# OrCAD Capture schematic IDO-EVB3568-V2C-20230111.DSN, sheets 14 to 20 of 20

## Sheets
14 P15. Ethernet-GEPHY_RGMII1_M1: size A2; title: IDO-EVB3568-V2; note: Ethernet-GEPHY_RGMII1
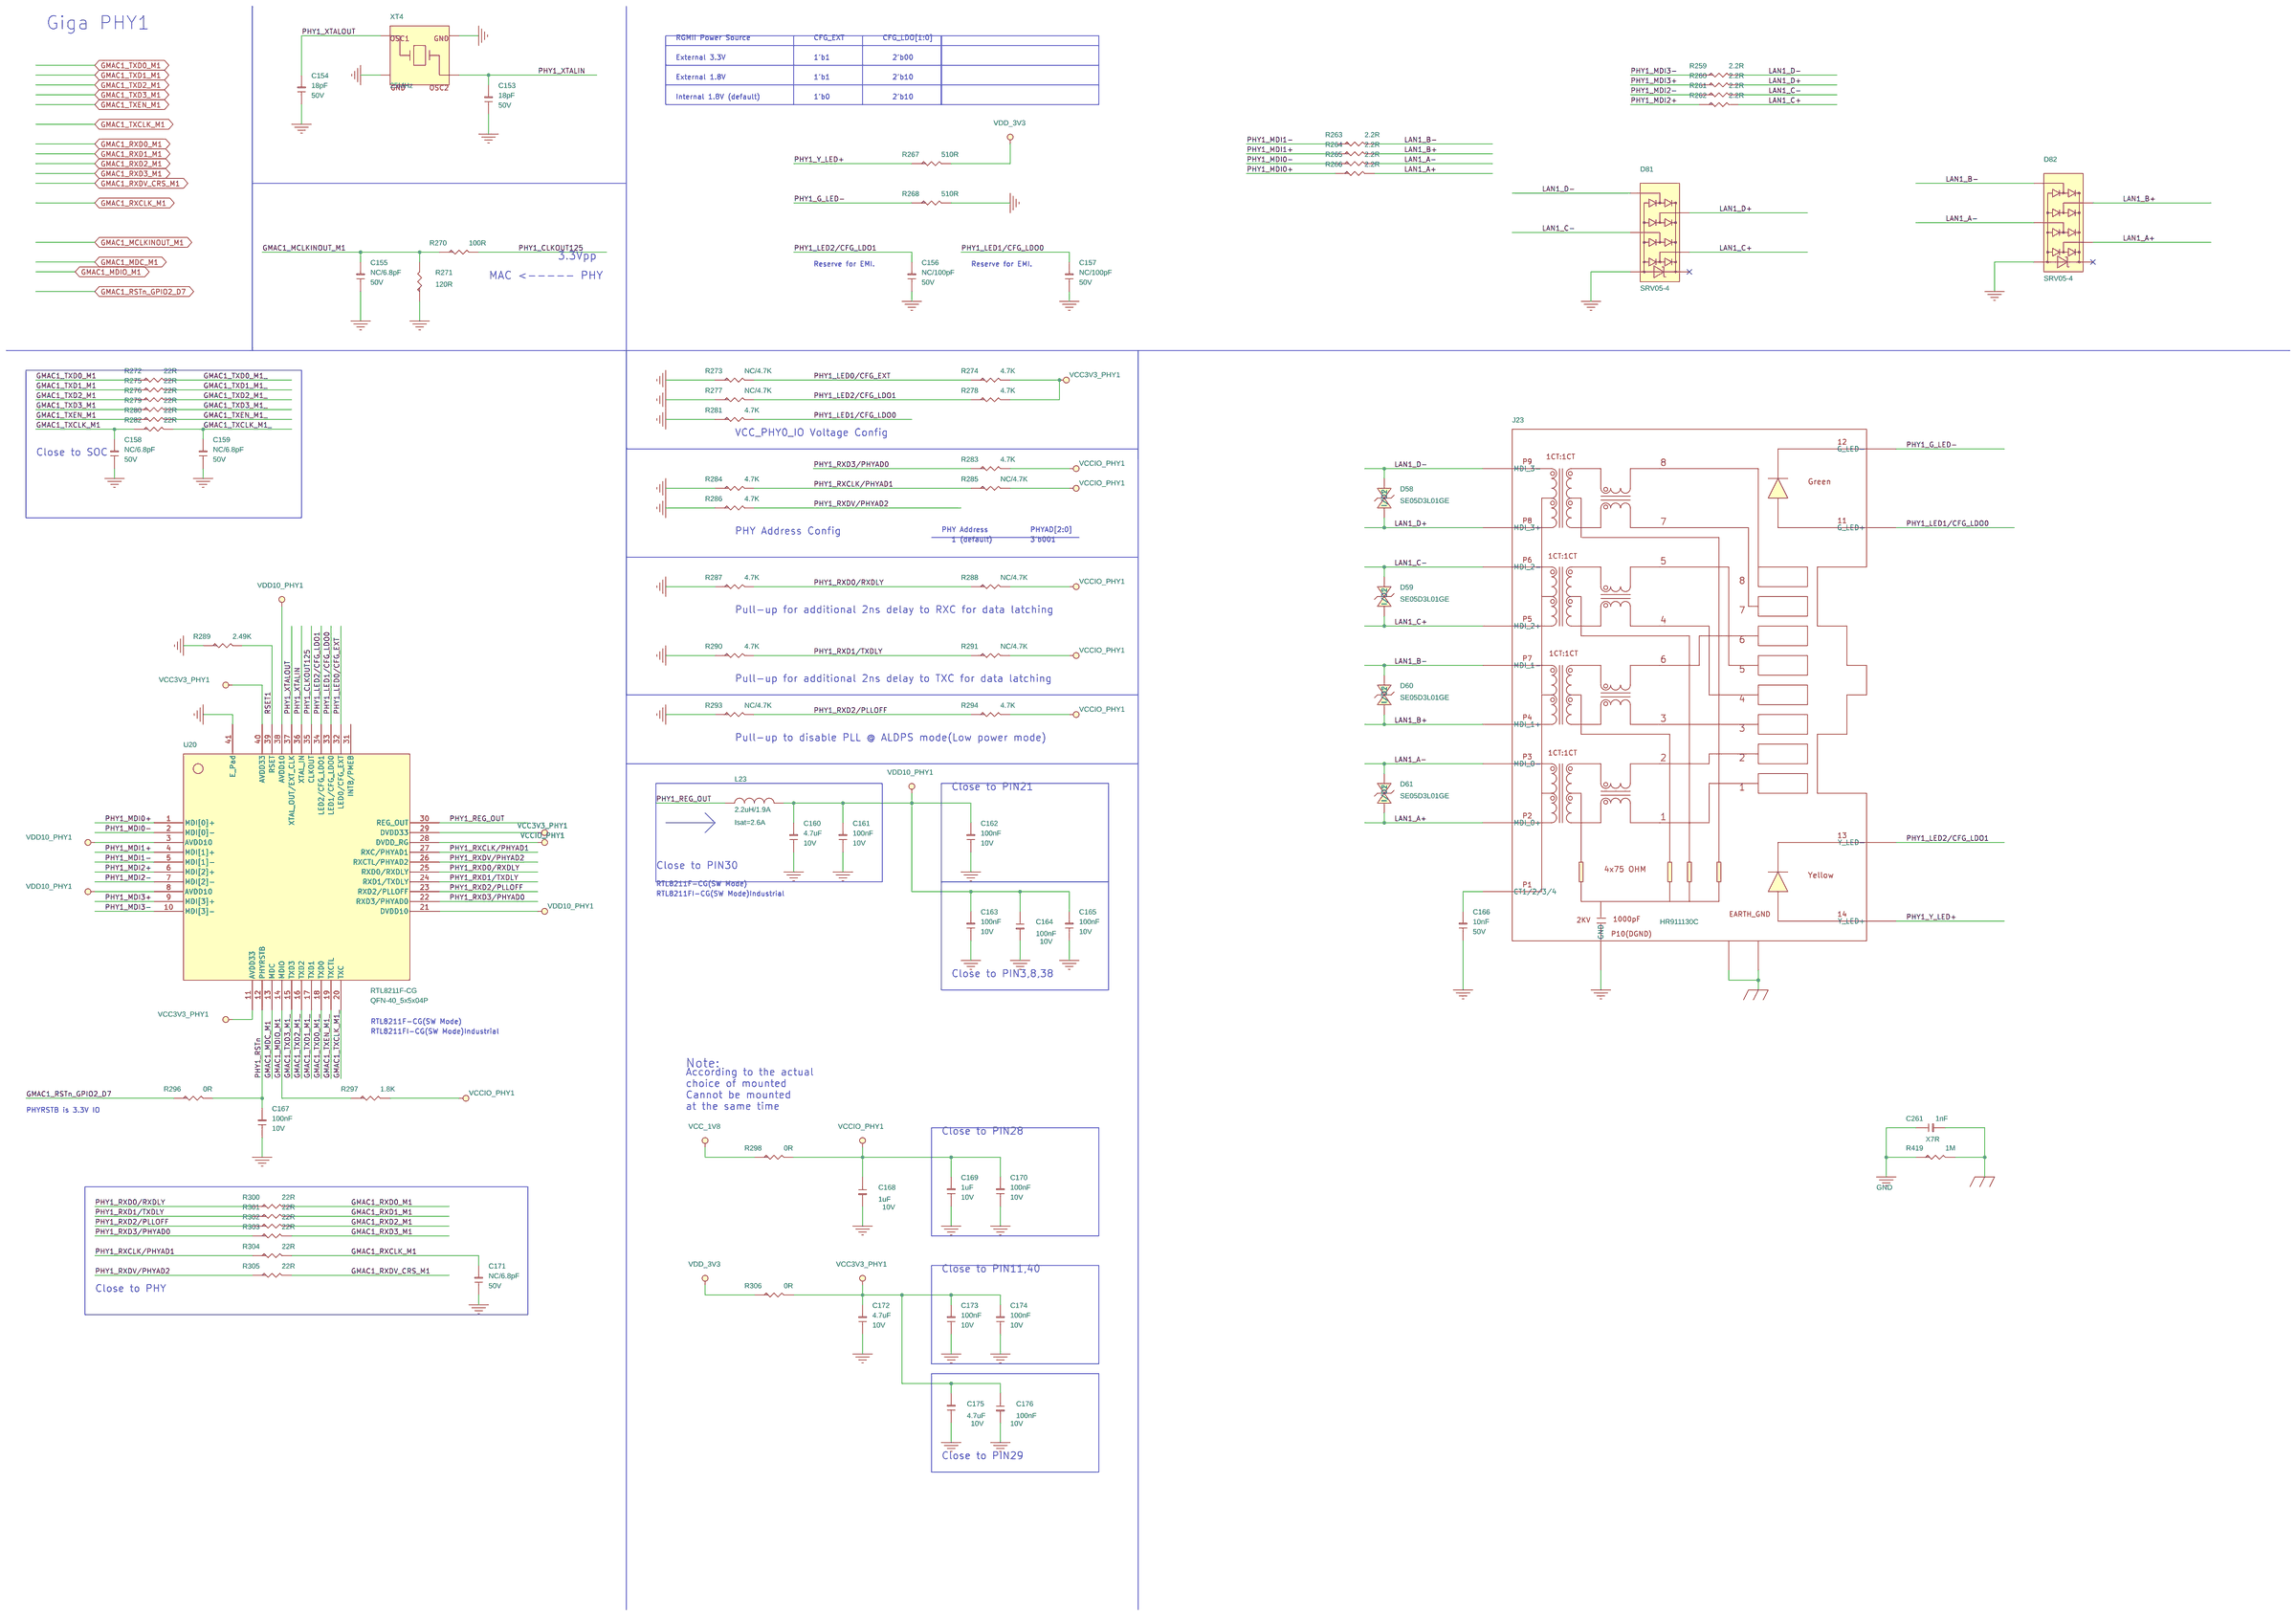
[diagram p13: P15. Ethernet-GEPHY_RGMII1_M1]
15 P16. IO: size A3; title: EST3568-V2; note: IO扩展
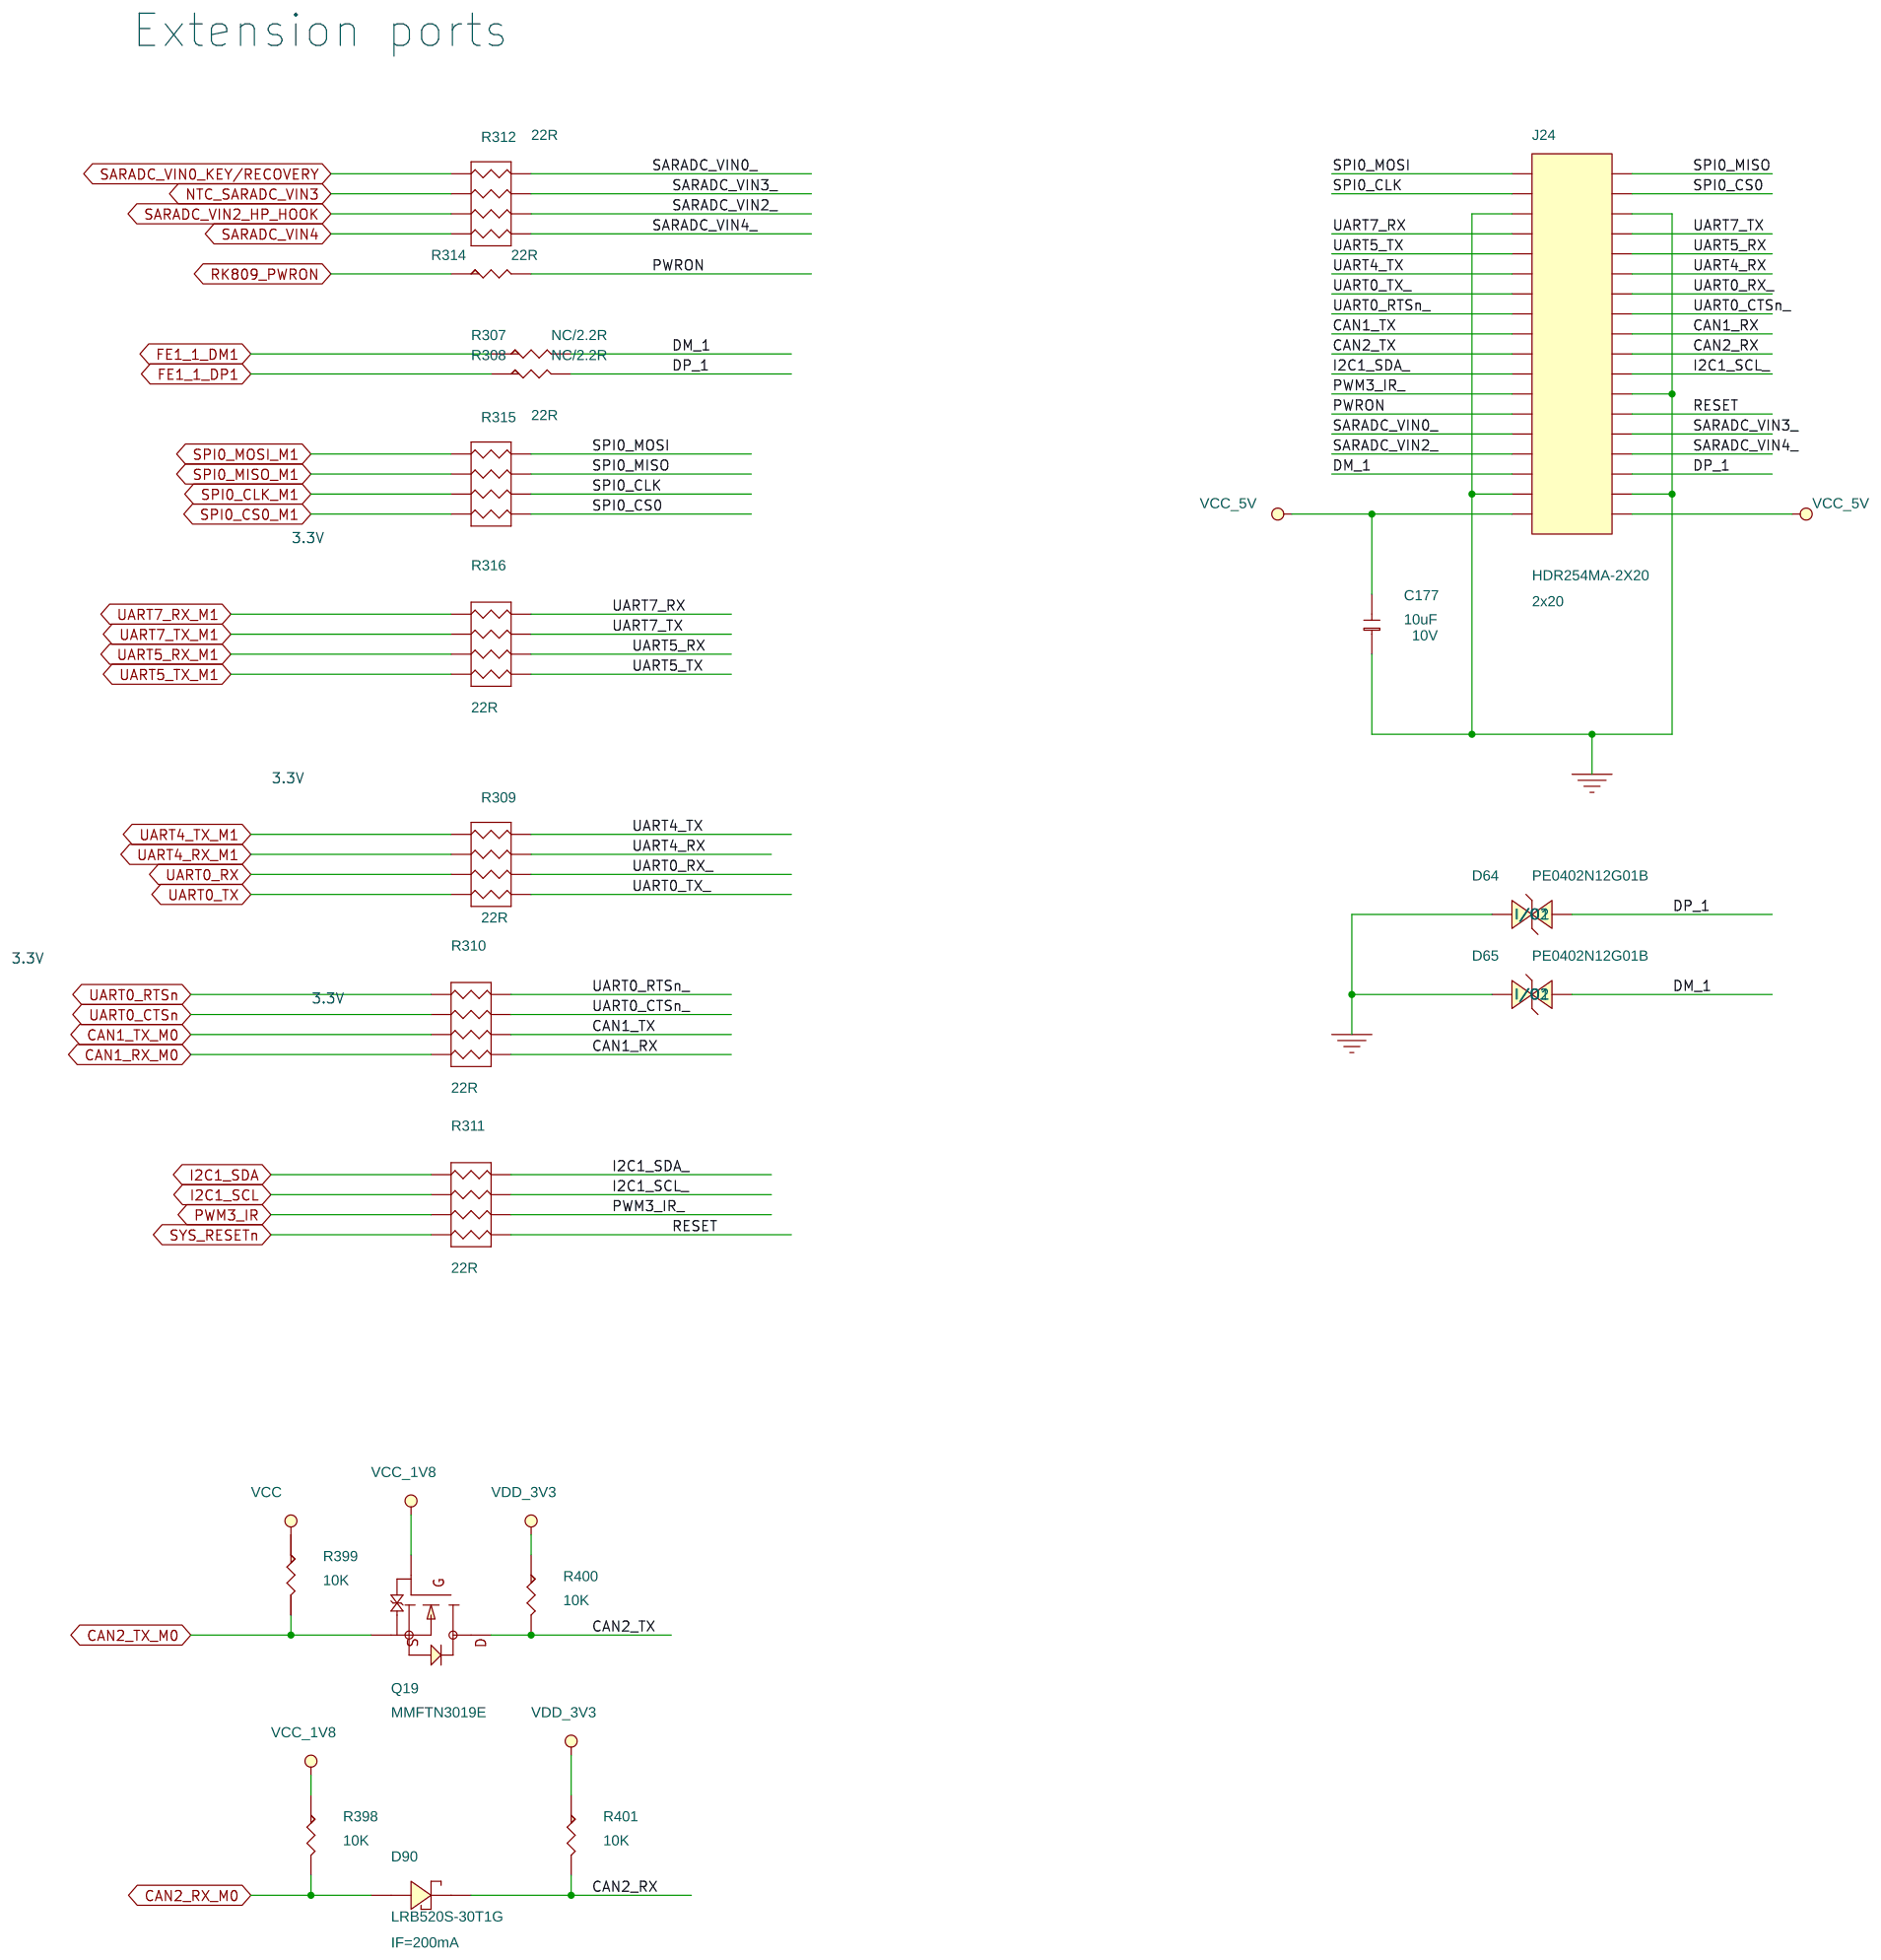
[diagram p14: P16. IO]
16 P19.PCIE2.0: size A3; title: EST3568-V2; note: MINI_PCIE
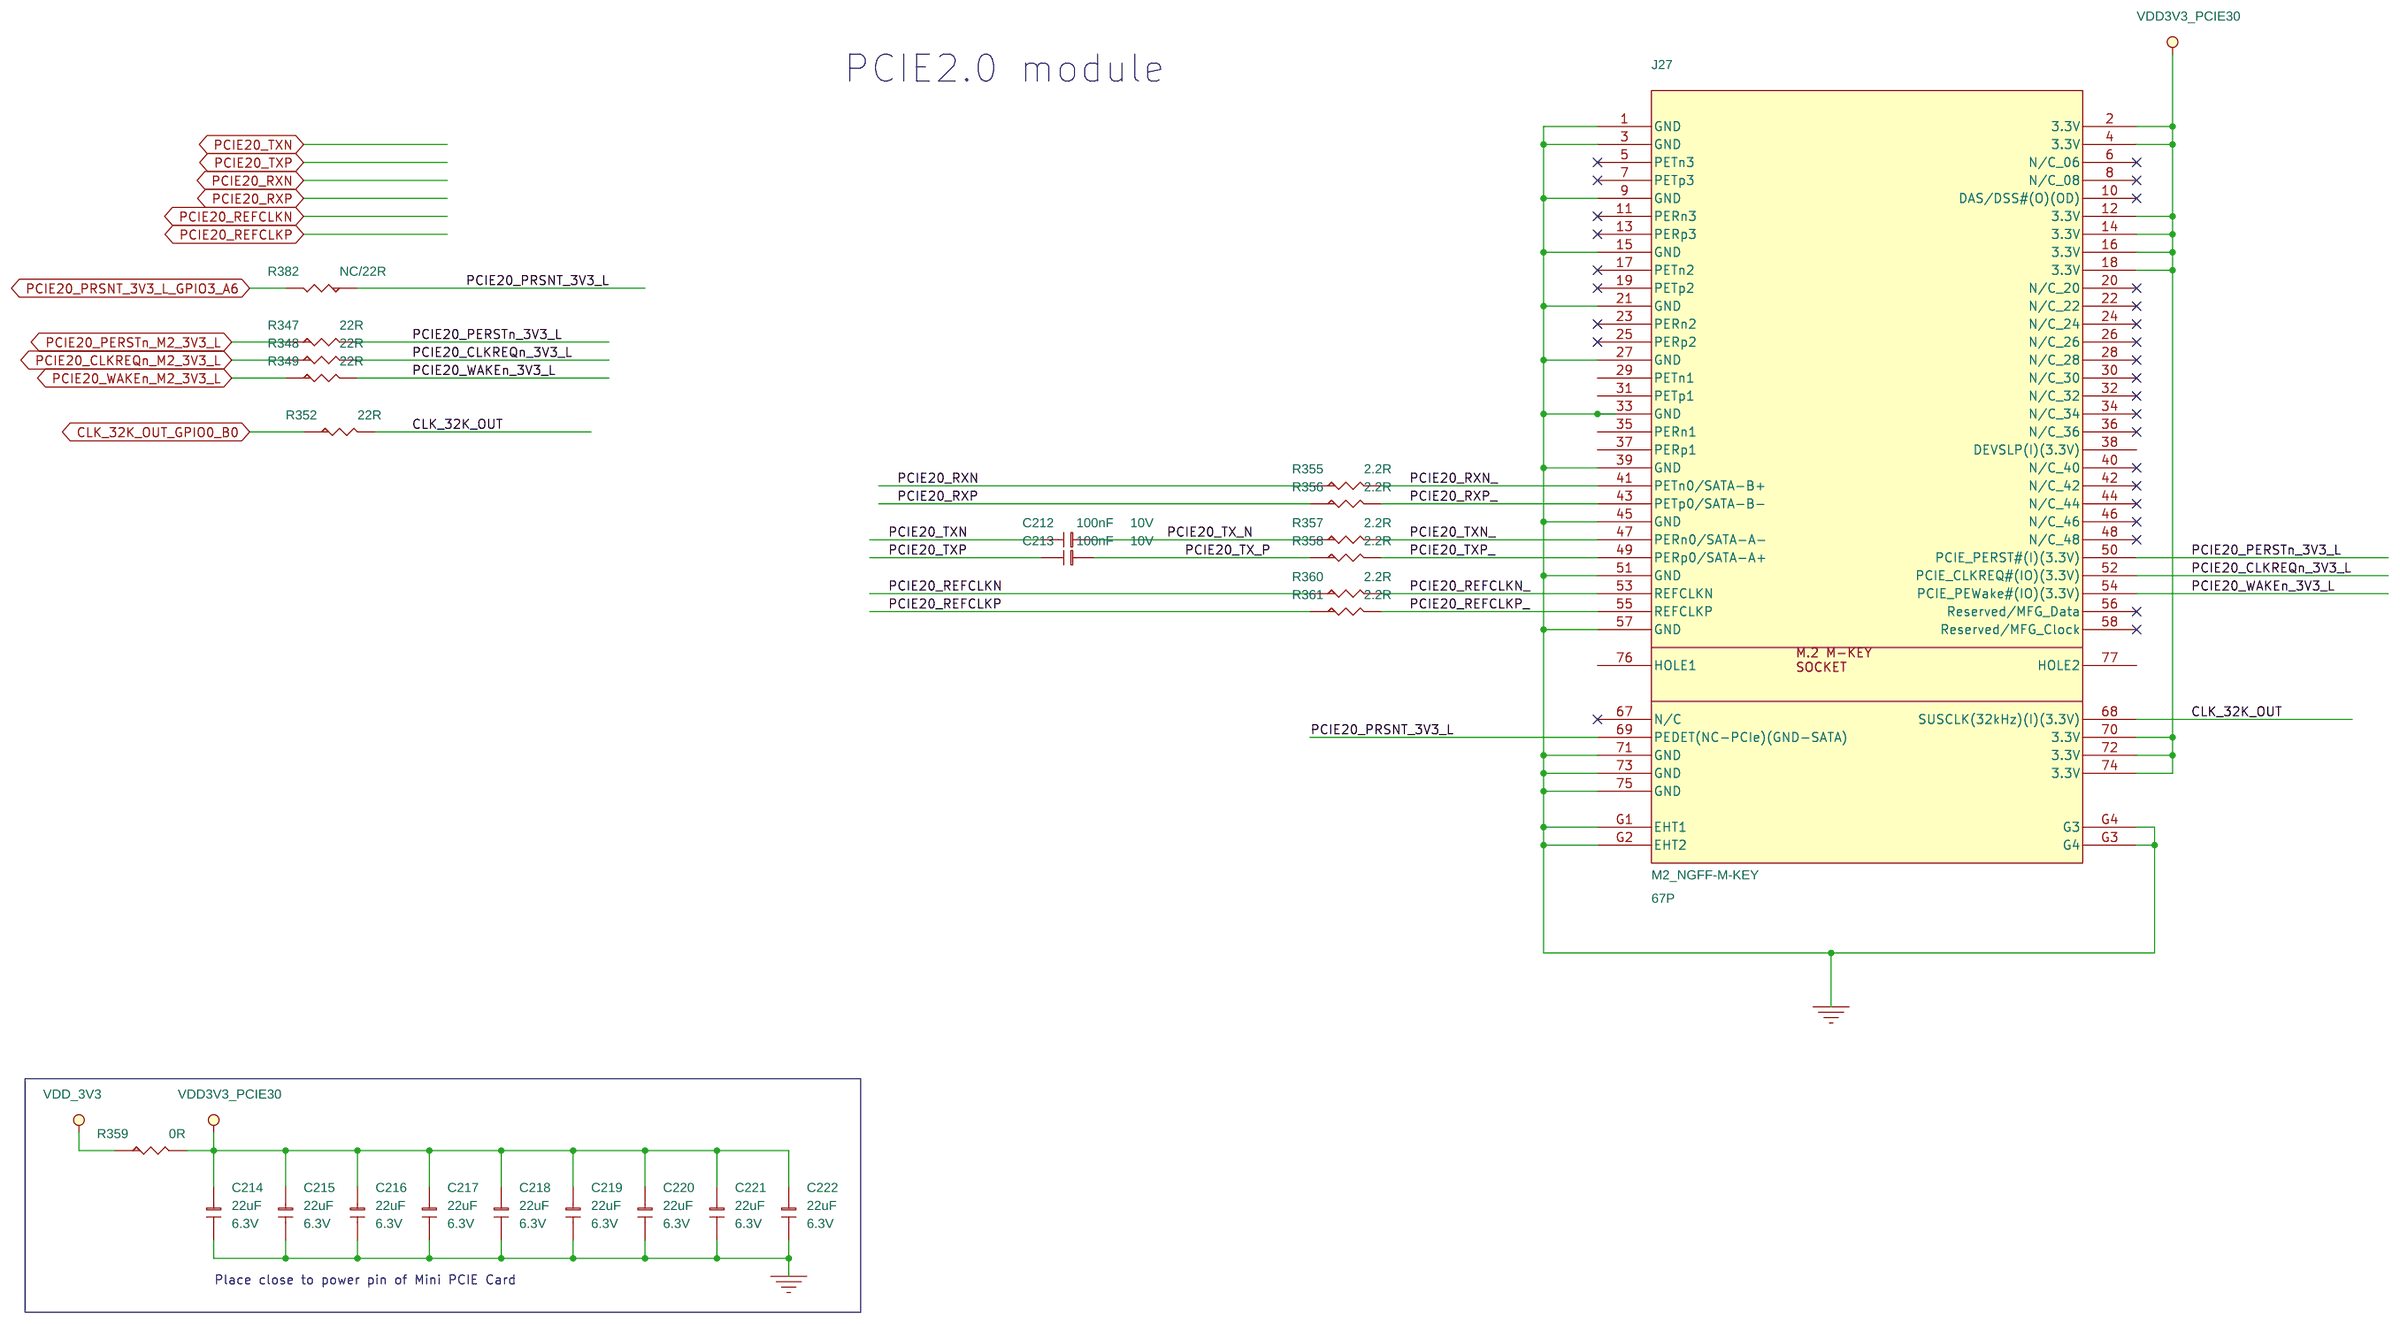
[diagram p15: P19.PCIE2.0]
17 P20.EDP: size A4; title: IDO-EVB3568-V2; note: VO-LCM_eDP TX
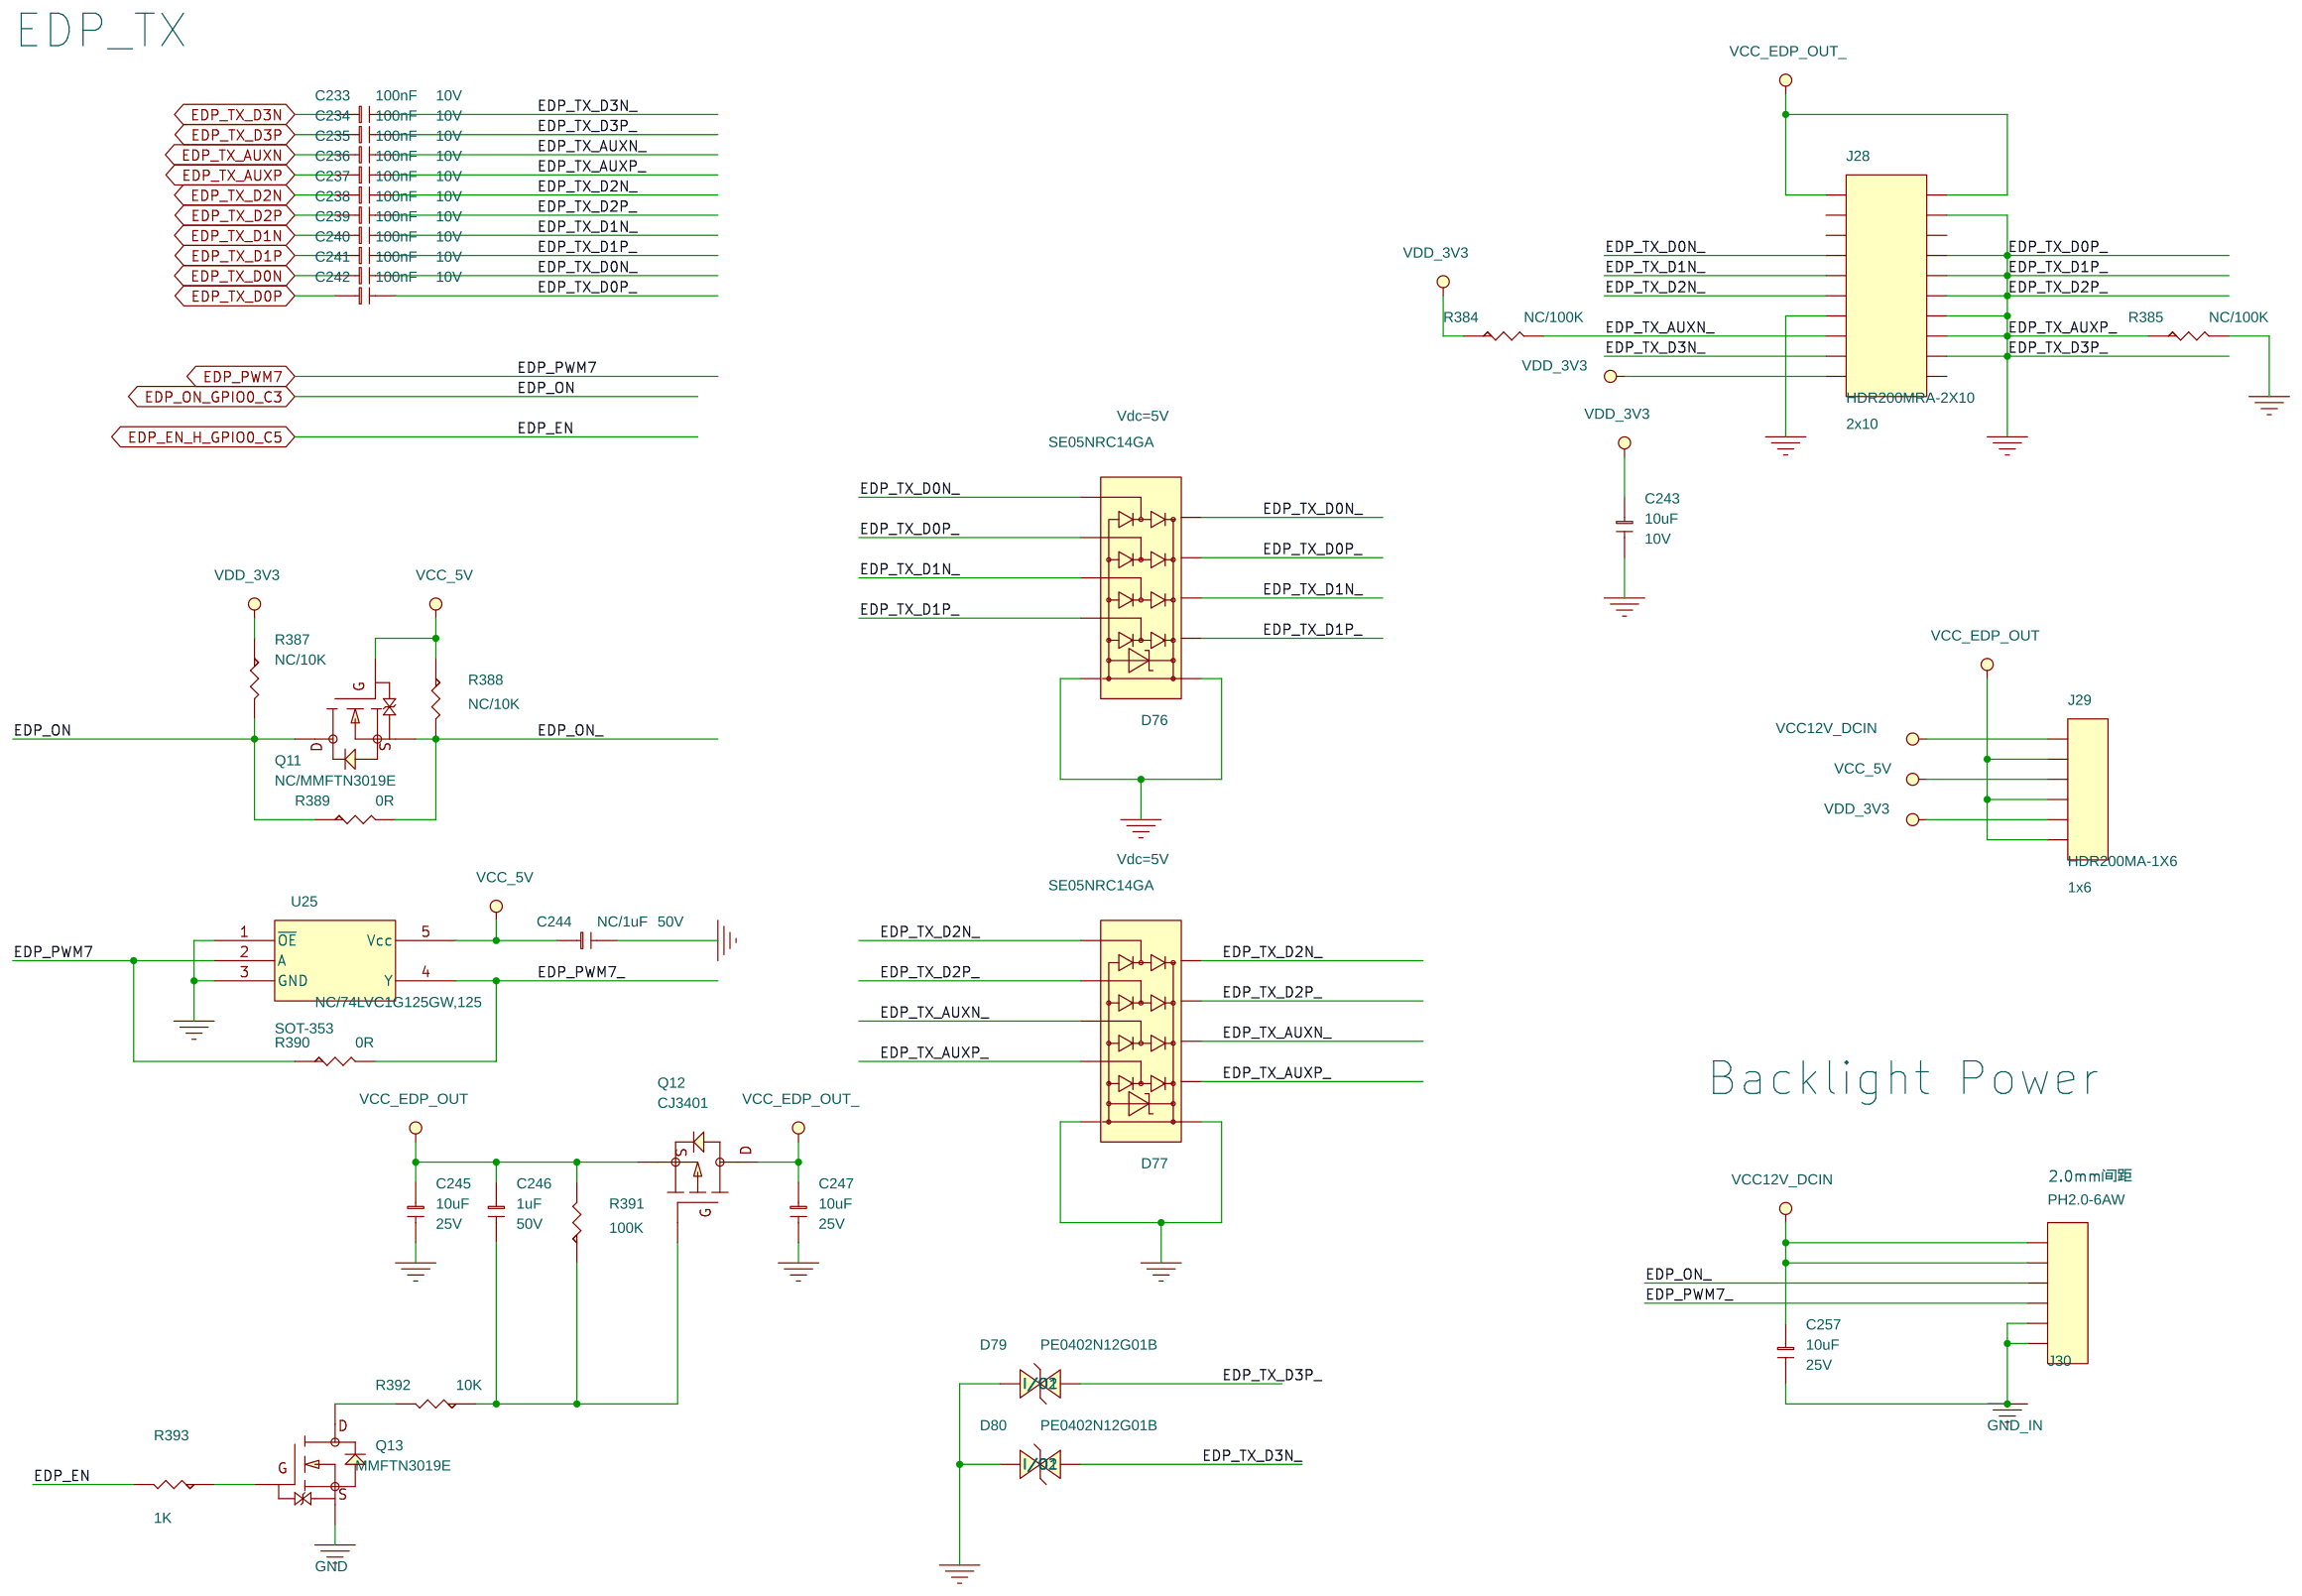
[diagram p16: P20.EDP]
18 P18. 4/5G MOD: size A3; title: EST3568-V2; note: MINI_PCIE
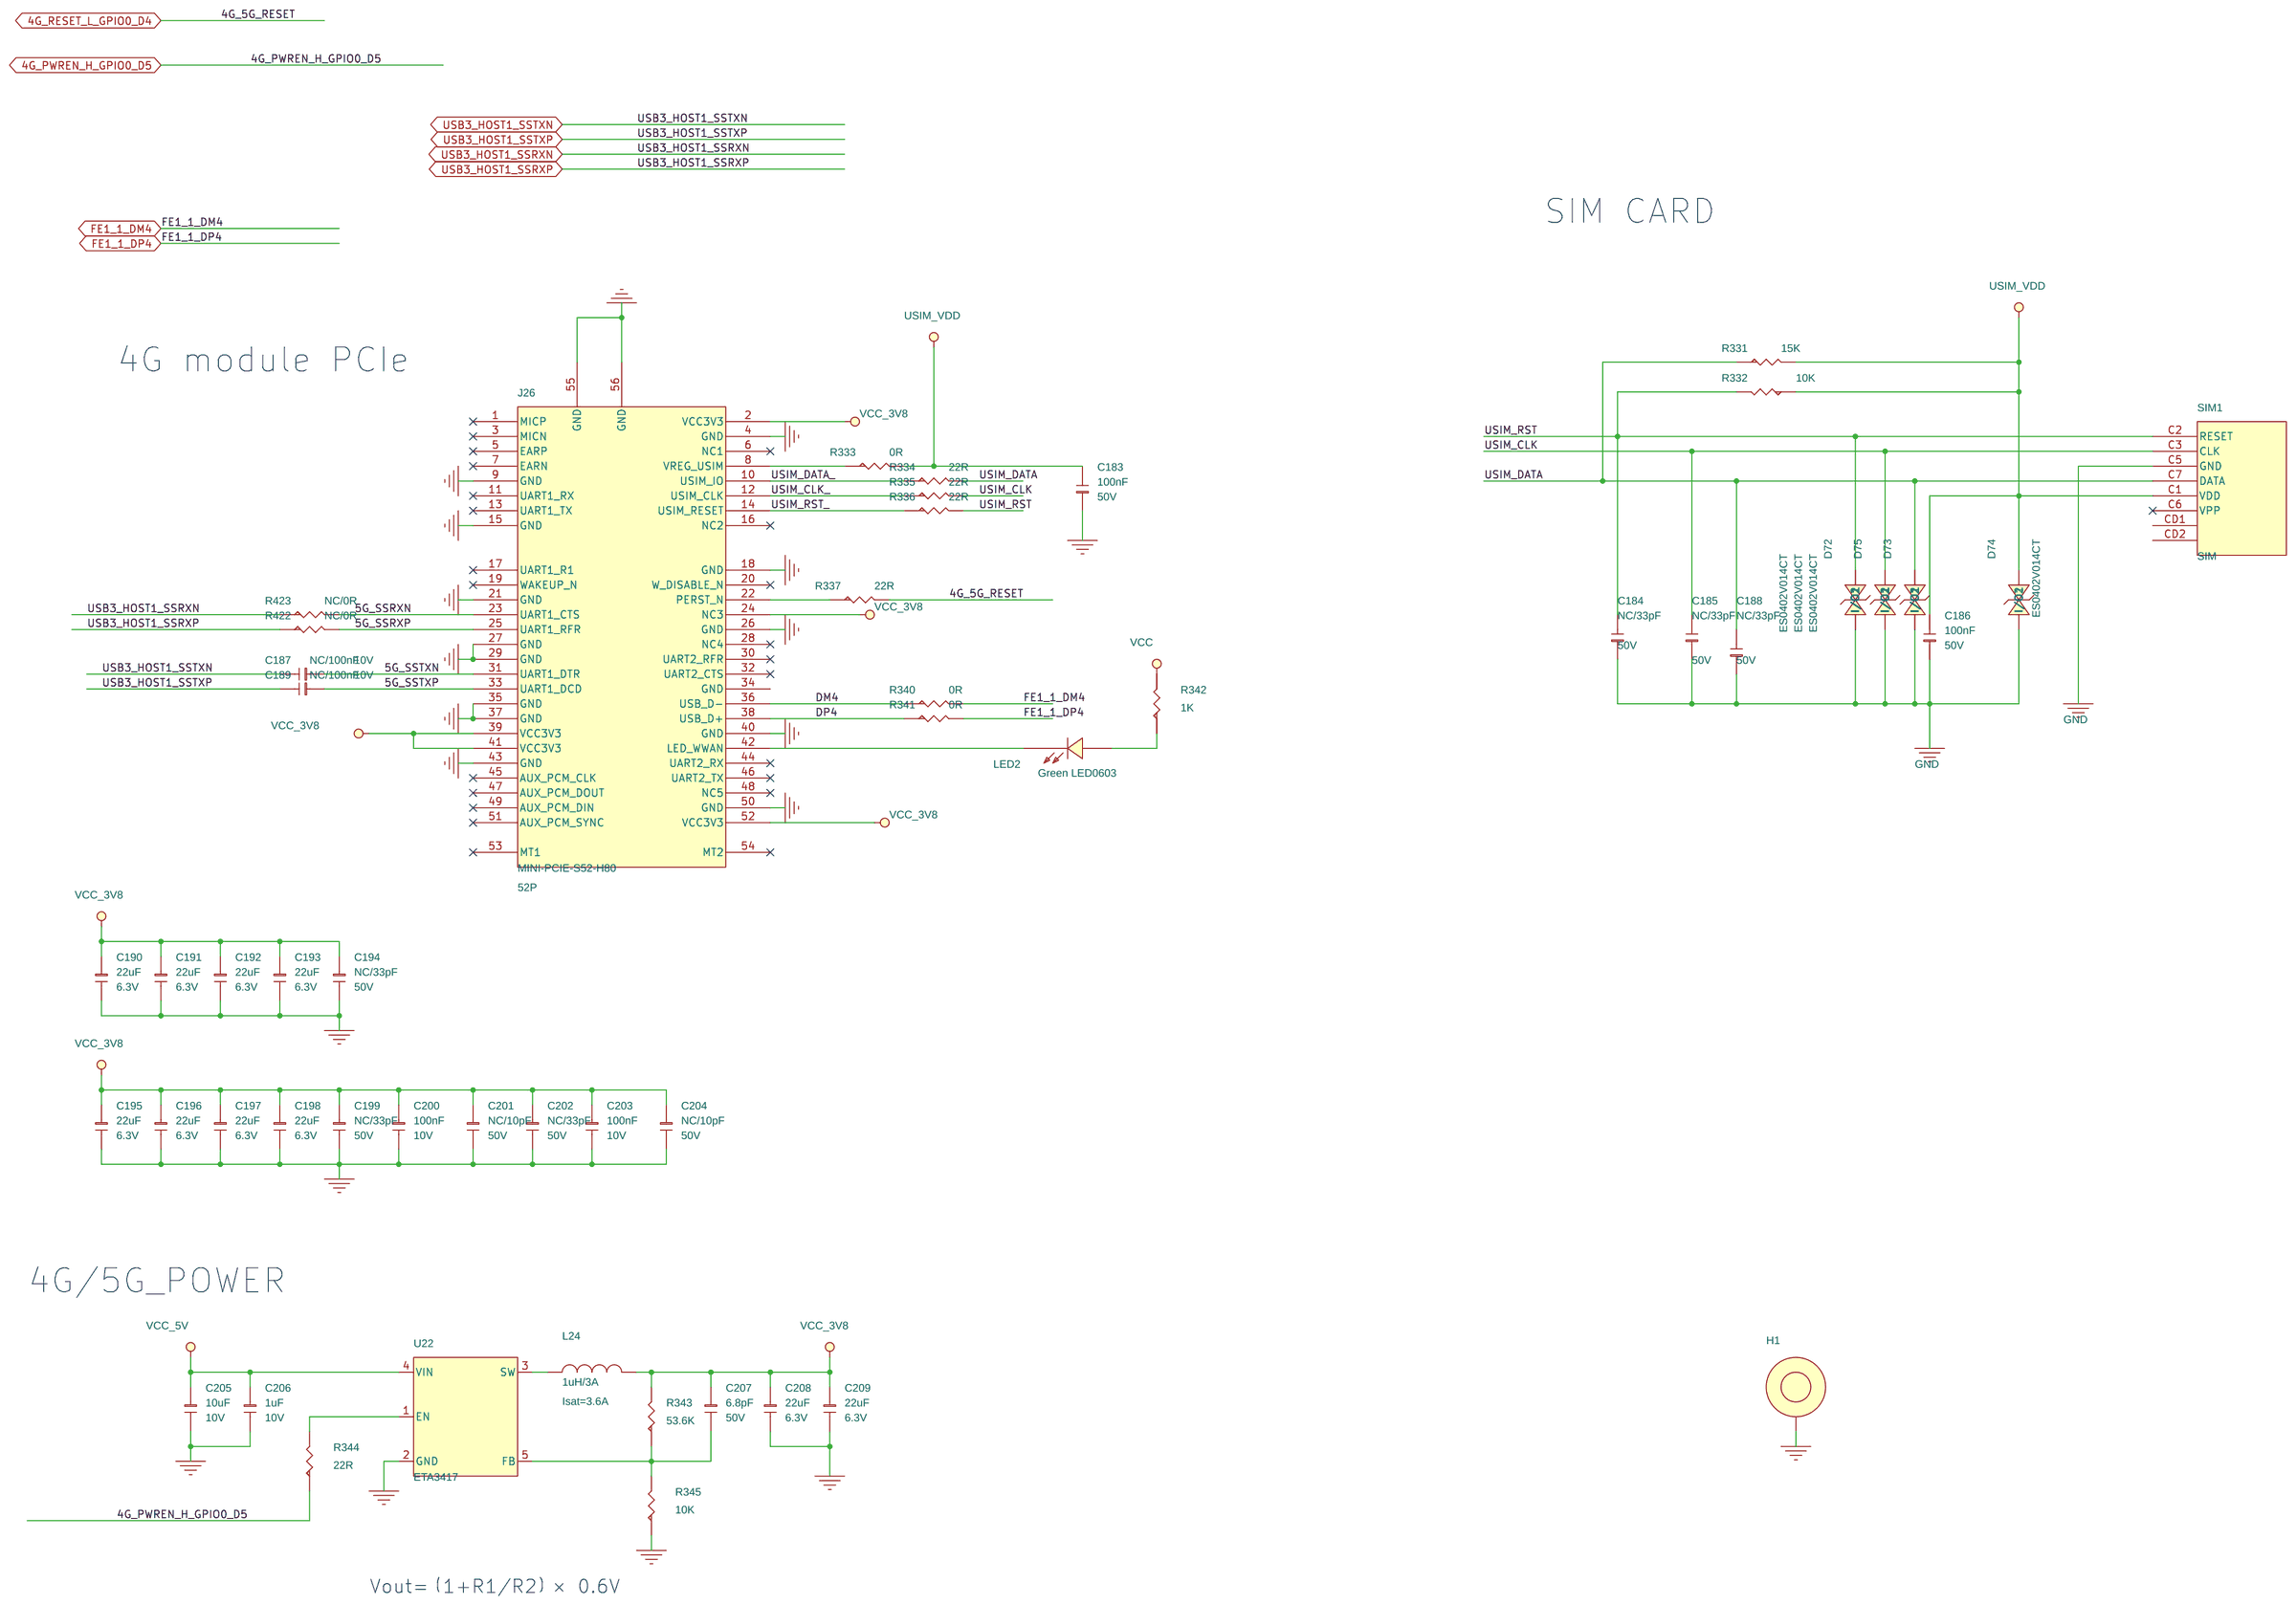
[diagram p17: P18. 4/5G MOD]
19 P17. RTC/RECOVERY: size A4; title: IDO-EVB3568-V2; note: RTC &I KEY
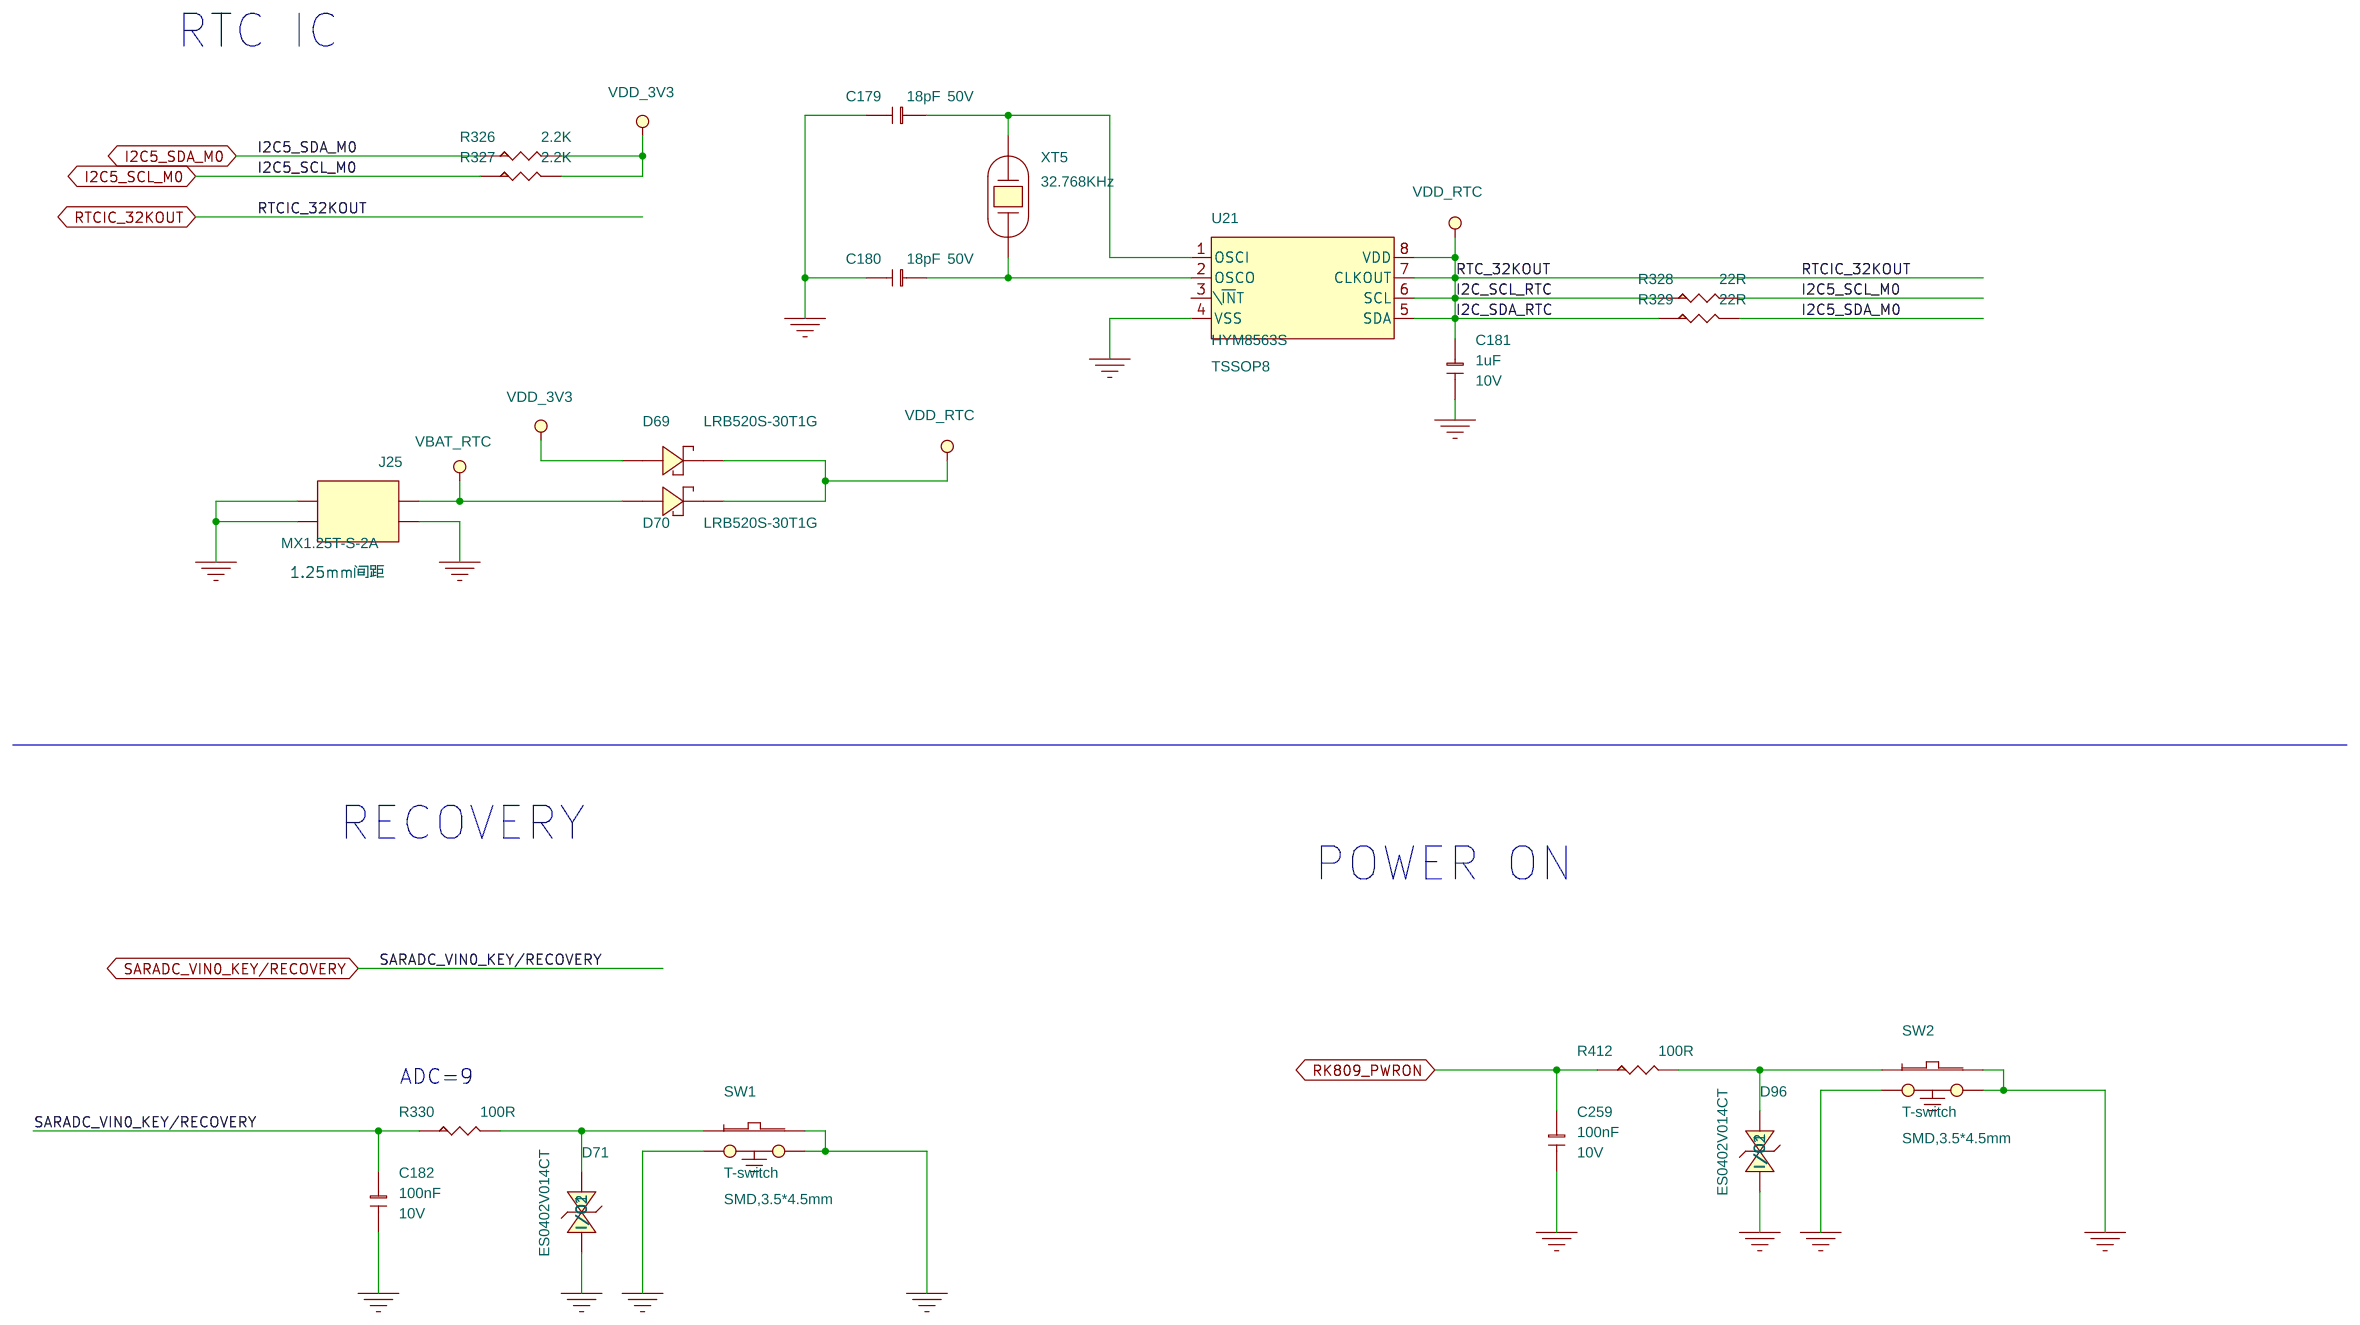
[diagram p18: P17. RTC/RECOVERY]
20 P13. WIFI/BT-SDMMC1_1T1R + UART: size A3; title: IDO-EVB3568-V2; note: WIFI&BT
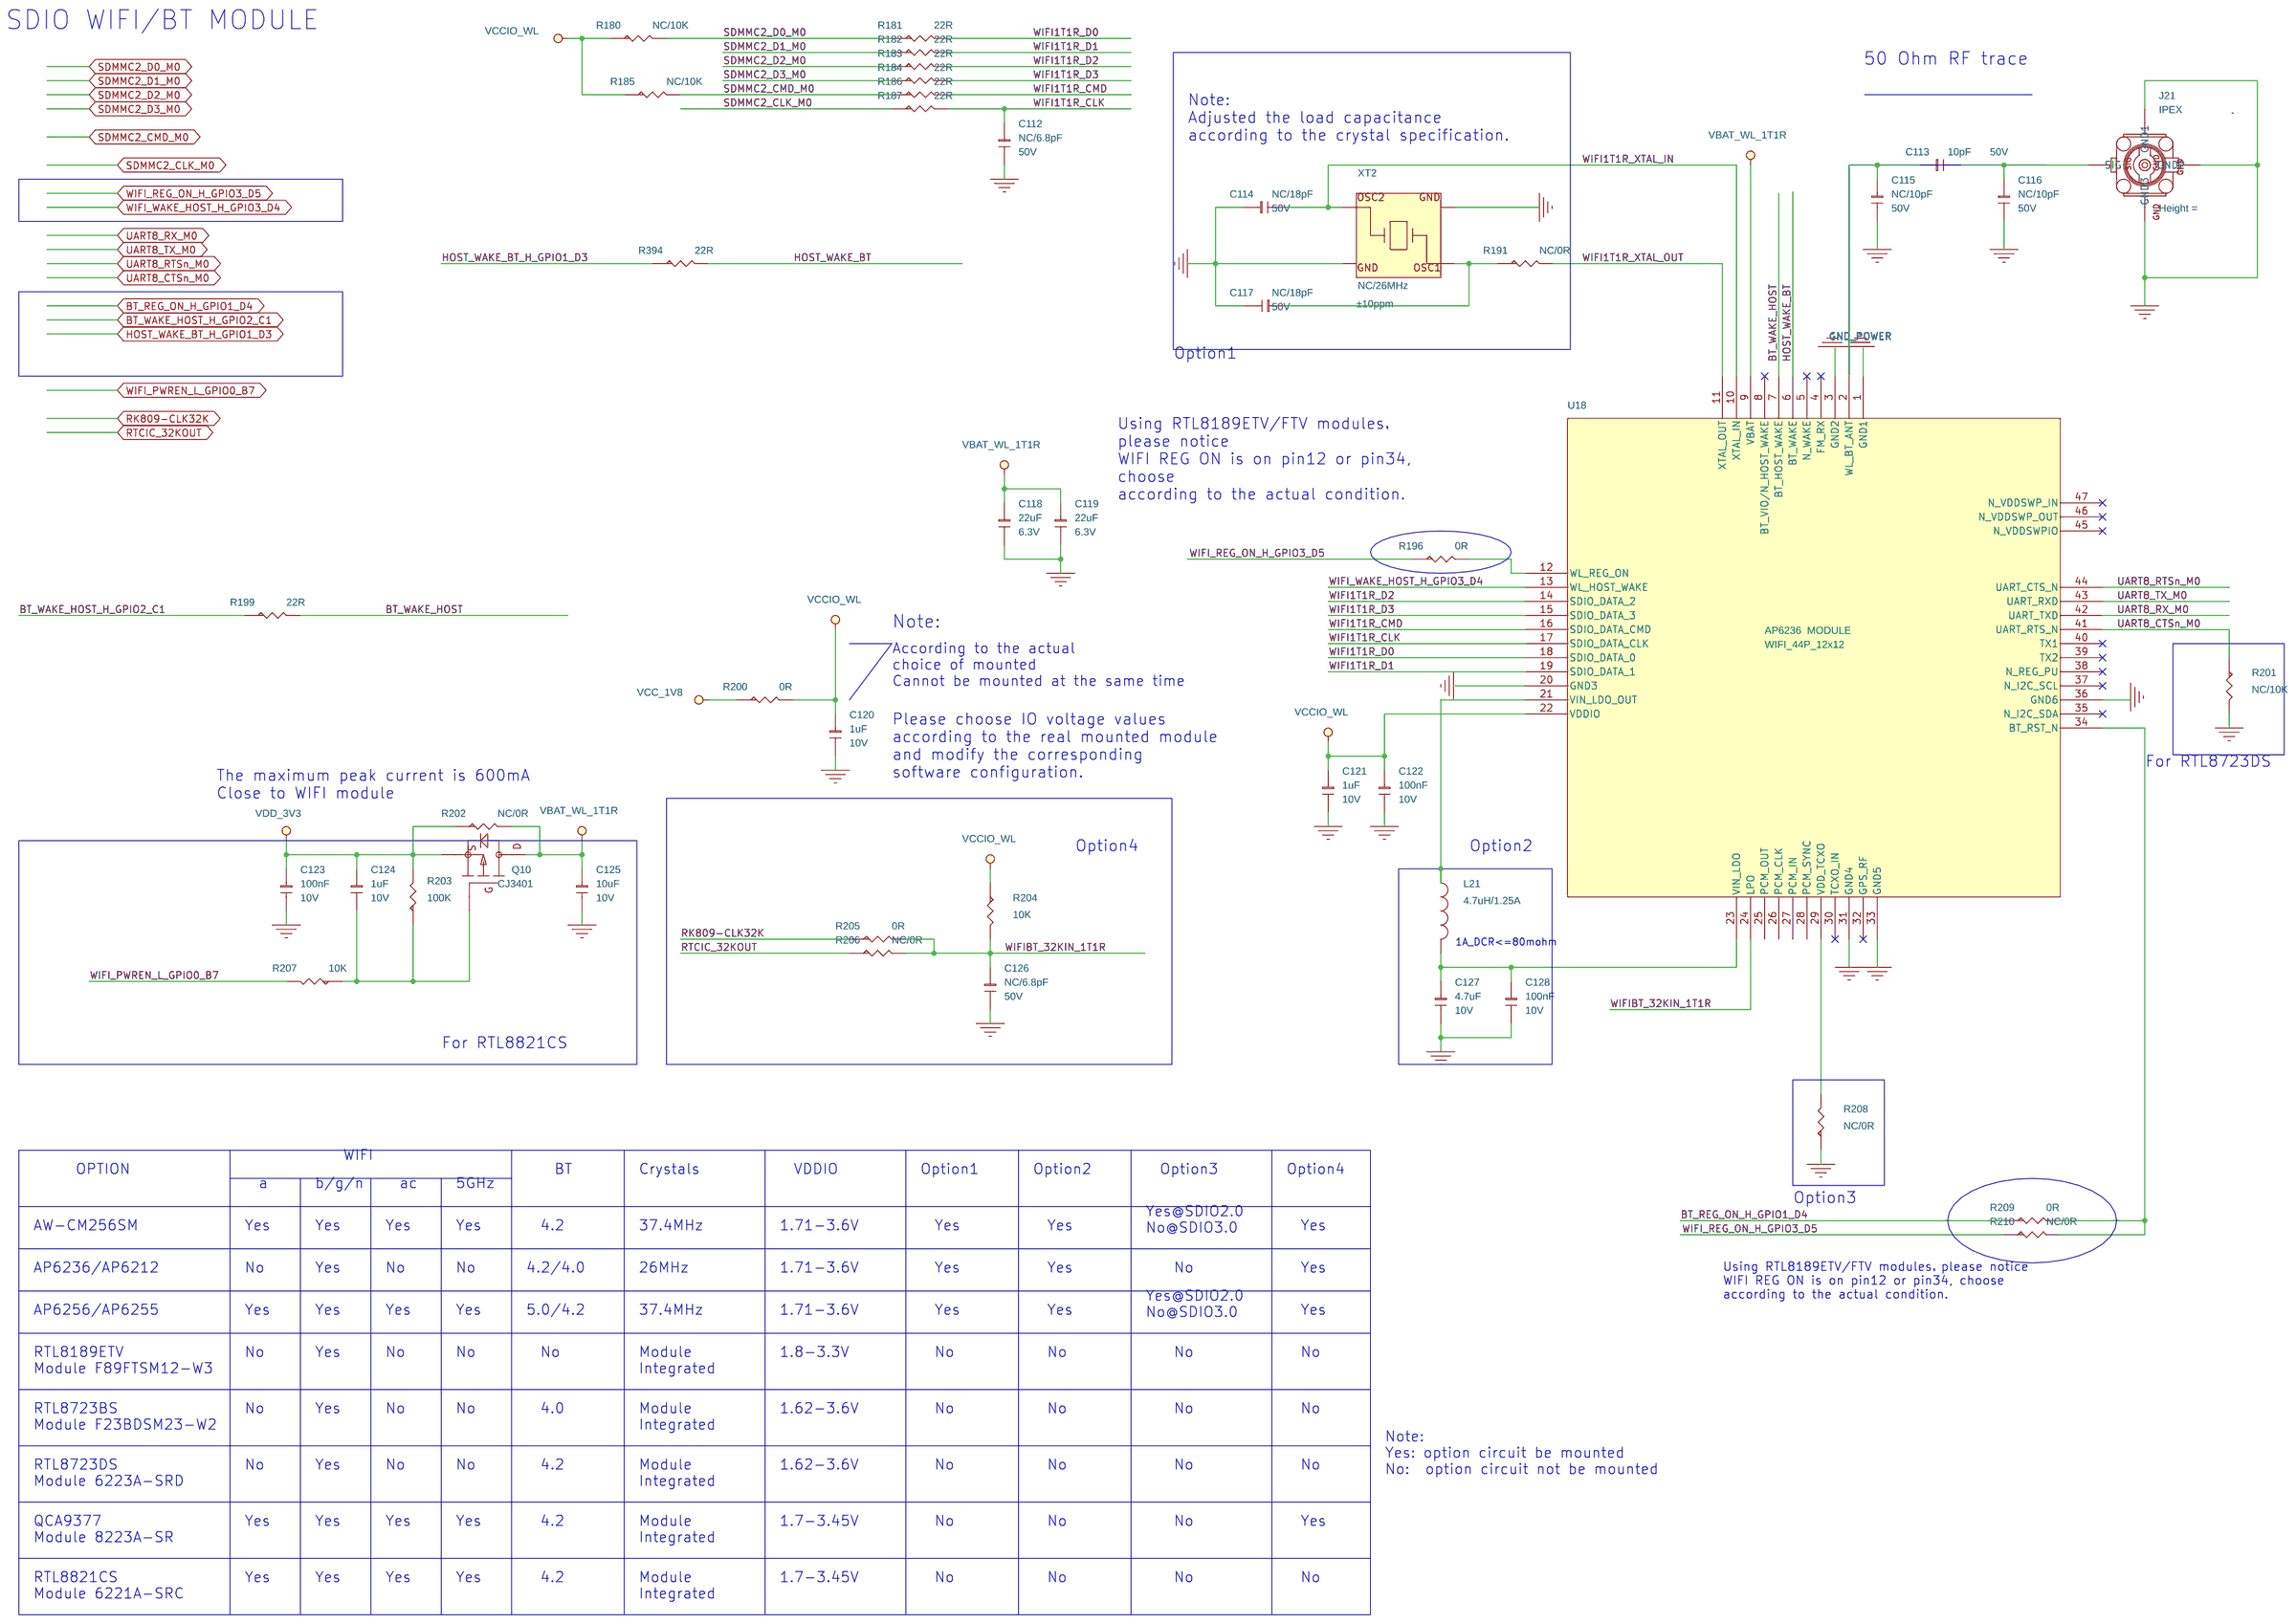
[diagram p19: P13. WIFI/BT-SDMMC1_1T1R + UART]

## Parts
sheet P13. WIFI/BT-SDMMC1_1T1R + UART
C112  NC/6.8pF  [C0402]
C113  10pF  [C0402]
C114  NC/18pF  [C0402]
C115  NC/10pF  [C0402]
C116  NC/10pF  [C0402]
C117  NC/18pF  [C0402]
C118  22uF  [C0603]
C119  22uF  [C0603]
C120  1uF  [C0402]
C121  1uF  [C0402]
C122  100nF  [C0402]
C123  100nF  [C0402]
C124  1uF  [C0402]
C125  10uF  [C0603]
C126  NC/6.8pF  [C0402]
C127  4.7uF  [C0402]
C128  100nF  [C0402]
J21  IPEX  [IPEX-001E]
L21  4.7uH/1.25A  [IND_252012]
Q10  CJ3401  [SOT23]
R180  NC/10K  [R0402]
R181  22R  [R0402]
R182  22R  [R0402]
R183  22R  [R0402]
R184  22R  [R0402]
R185  NC/10K  [R0402]
R186  22R  [R0402]
R187  22R  [R0402]
R191  NC/0R  [R0402]
R196  0R  [R0402]
R199  22R  [R0402]
R200  0R  [R0402]
R201  NC/10K  [R0402]
R202  NC/0R  [R0805]
R203  100K  [R0402]
R204  10K  [R0402]
R205  0R  [R0402]
R206  NC/0R  [R0402]
R207  10K  [R0402]
R208  NC/0R  [R0402]
R209  0R  [R0402]
R210  NC/0R  [R0402]
R394  22R  [R0402]
U18  AP6236  MODULE  [WIFI_44P_12x12]
XT2  NC/26MHz  [XTAL_32X25_4P]
sheet P15. Ethernet-GEPHY_RGMII1_M1
C153  18pF  [C0402]
C154  18pF  [C0402]
C155  NC/6.8pF  [C0402]
C156  NC/100pF  [C0402]
C157  NC/100pF  [C0402]
C158  NC/6.8pF  [C0402]
C159  NC/6.8pF  [C0402]
C160  4.7uF  [C0402]
C161  100nF  [C0402]
C162  100nF  [C0402]
C163  100nF  [C0402]
C164  100nF  [C0402]
C165  100nF  [C0402]
C166  10nF  [C0402]
C167  100nF  [C0402]
C168  1uF  [C0402]
C169  1uF  [C0402]
C170  100nF  [C0402]
C171  NC/6.8pF  [C0402]
C172  4.7uF  [C0402]
C173  100nF  [C0402]
C174  100nF  [C0402]
C175  4.7uF  [C0402]
C176  100nF  [C0402]
C261  1nF  [C1206]
D58  SE05D3L01GE  [SOD323]
D59  SE05D3L01GE  [SOD323]
D60  SE05D3L01GE  [SOD323]
D61  SE05D3L01GE  [SOD323]
D81  SRV05-4  [SOT23-6]
D82  SRV05-4  [SOT23-6]
J23  HR911130C  [RJ45-TH_HR911130A]
L23  2.2uH/1.9A  [IND_252012]
R259  2.2R  [R0402]
R260  2.2R  [R0402]
R261  2.2R  [R0402]
R262  2.2R  [R0402]
R263  2.2R  [R0402]
R264  2.2R  [R0402]
R265  2.2R  [R0402]
R266  2.2R  [R0402]
R267  510R  [R0402]
R268  510R  [R0402]
R270  100R  [R0402]
R271  120R  [R0402]
R272  22R  [R0402]
R273  NC/4.7K  [R0402]
R274  4.7K  [R0402]
R275  22R  [R0402]
R276  22R  [R0402]
R277  NC/4.7K  [R0402]
R278  4.7K  [R0402]
R279  22R  [R0402]
R280  22R  [R0402]
R281  4.7K  [R0402]
R282  22R  [R0402]
R283  4.7K  [R0402]
R284  4.7K  [R0402]
R285  NC/4.7K  [R0402]
R286  4.7K  [R0402]
R287  4.7K  [R0402]
R288  NC/4.7K  [R0402]
R289  2.49K  [R0402]
R290  4.7K  [R0402]
R291  NC/4.7K  [R0402]
R293  NC/4.7K  [R0402]
R294  4.7K  [R0402]
R296  0R  [R0402]
R297  1.8K  [R0402]
R298  0R  [R0402]
R300  22R  [R0402]
R301  22R  [R0402]
R302  22R  [R0402]
R303  22R  [R0402]
R304  22R  [R0402]
R305  22R  [R0402]
R306  0R  [R0402]
R419  1M  [R0805]
U20  RTL8211F-CG  [QFN-40_5x5x04P]
XT4  25MHz  [xtal_32x25_4p]
sheet P16. IO
C177  10uF  [C0603]
D64  PE0402N12G01B  [V0402]
D65  PE0402N12G01B  [V0402]
D90  LRB520S-30T1G  [SOD523]
J24  HDR254MA-2X20  [HDR254MA-2X18]
Q19  MMFTN3019E  [SOT523]
R307  NC/2.2R  [R0402]
R308  NC/2.2R  [R0402]
R309  22R  [RN_0402X4]
R310  22R  [RN_0402X4]
R311  22R  [RN_0402X4]
R312  22R  [RN_0402X4]
R314  22R  [R0402]
R315  22R  [RN_0402X4]
R316  22R  [RN_0402X4]
R398  10K  [R0402]
R399  10K  [R0402]
R400  10K  [R0402]
R401  10K  [R0402]
sheet P17. RTC/RECOVERY
C179  18pF  [C0402]
C180  18pF  [C0402]
C181  1uF  [C0402]
C182  100nF  [C0402]
C259  100nF  [C0402]
D69  LRB520S-30T1G  [SOD523]
D70  LRB520S-30T1G  [SOD523]
D71  ES0402V014CT  [V0402]
D96  ES0402V014CT  [V0402]
J25  MX1.25T-S-2A  [MX125T-S-2A]
R326  2.2K  [R0402]
R327  2.2K  [R0402]
R328  22R  [R0402]
R329  22R  [R0402]
R330  100R  [R0402]
R412  100R  [R0402]
SW1  T-switch  [PB-SIDE-S-3_5x4_5]
SW2  T-switch  [PB-SIDE-S-3_5x4_5]
U21  HYM8563S  [TSSOP-8]
XT5  32.768KHz  [XTAL_32X15_2P]
sheet P18. 4/5G MOD
C183  100nF  [C0402]
C184  NC/33pF  [C0402]
C185  NC/33pF  [C0402]
C186  100nF  [C0402]
C187  NC/100nF  [C0402]
C188  NC/33pF  [C0402]
C189  NC/100nF  [C0402]
C190  22uF  [C0603]
C191  22uF  [C0603]
C192  22uF  [C0603]
C193  22uF  [C0603]
C194  NC/33pF  [C0402]
C195  22uF  [C0603]
C196  22uF  [C0603]
C197  22uF  [C0603]
C198  22uF  [C0603]
C199  NC/33pF  [C0402]
C200  100nF  [C0402]
C201  NC/10pF  [C0402]
C202  NC/33pF  [C0402]
C203  100nF  [C0402]
C204  NC/10pF  [C0402]
C205  10uF  [C0603]
C206  1uF  [C0402]
C207  6.8pF  [C0402]
C208  22uF  [C0603]
C209  22uF  [C0603]
D72  ES0402V014CT  [V0402]
D73  ES0402V014CT  [V0402]
D74  ES0402V014CT  [V0402]
D75  ES0402V014CT  [V0402]
H1  HOLE  [4G_MTG170_450]
J26  MINI-PCIE-S52-H80  [M_MINIPCIE_SOCKET_CK]
L24  1uH/3A  [IND_252012]
LED2  Green LED0603  [LED0603]
R331  15K  [R0402]
R332  10K  [R0402]
R333  0R  [R0603]
R334  22R  [R0402]
R335  22R  [R0402]
R336  22R  [R0402]
R337  22R  [R0402]
R340  0R  [R0402]
R341  0R  [R0402]
R342  1K  [R0402]
R343  53.6K  [R0402]
R344  22R  [R0402]
R345  10K  [R0402]
R422  NC/0R  [R0402]
R423  NC/0R  [R0402]
SIM1  SIM  [SIM-91288-021]
U22  ETA3417  [SOT23-5]
sheet P19.PCIE2.0
C212  100nF  [C0402]
C213  100nF  [C0402]
C214  22uF  [C0603]
C215  22uF  [C0603]
C216  22uF  [C0603]
C217  22uF  [C0603]
C218  22uF  [C0603]
C219  22uF  [C0603]
C220  22uF  [C0603]
C221  22uF  [C0603]
C222  22uF  [C0603]
J27  M2_NGFF-M-KEY  [M2_NGFF-M-KEY]
R347  22R  [R0402]
R348  22R  [R0402]
R349  22R  [R0402]
R352  22R  [R0402]
R355  2.2R  [R0402]
R356  2.2R  [R0402]
R357  2.2R  [R0402]
R358  2.2R  [R0402]
R359  0R  [R0603]
R360  2.2R  [R0402]
R361  2.2R  [R0402]
R382  NC/22R  [R0402]
sheet P20.EDP
C233  100nF  [C0402]
C234  100nF  [C0402]
C235  100nF  [C0402]
C236  100nF  [C0402]
C237  100nF  [C0402]
C238  100nF  [C0402]
C239  100nF  [C0402]
C240  100nF  [C0402]
C241  100nF  [C0402]
C242  100nF  [C0402]
C243  10uF  [C0603]
C244  NC/1uF  [C0603]
C245  10uF  [C0805]
C246  1uF  [C0603]
C247  10uF  [C0805]
C257  10uF  [C0805]
D76  SE05NRC14GA  [DFN2510-10L]
D77  SE05NRC14GA  [DFN2510-10L]
D79  PE0402N12G01B  [V0402]
D80  PE0402N12G01B  [V0402]
J28  HDR200MRA-2X10  [HDR200MRA-2X10]
J29  HDR200MA-1X6  [HDR200MA-1X6]
J30  PH2.0-6AW  [PH200-6AW]
Q11  NC/MMFTN3019E  [SOT523]
Q12  CJ3401  [SOT23]
Q13  MMFTN3019E  [SOT523]
R384  NC/100K  [R0402]
R385  NC/100K  [R0402]
R387  NC/10K  [R0402]
R388  NC/10K  [R0402]
R389  0R  [R0402]
R390  0R  [R0402]
R391  100K  [R0402]
R392  10K  [R0402]
R393  1K  [R0402]
U25  NC/74LVC1G125GW,125  [SOT353]

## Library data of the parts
C112 C126 C155 C158 C159 C171 C207 = C-0402: DSC1: ±0.25PF; DSC2: 50V; DSC3: C0G; ERP Number: 1010200056; ID: 18; Manufacture: 三星|国巨|村田; Part Name: 贴片电容; Part Number: C020102120018; Price: 0.01
C113 C115 C116 C201 C204 = C-0402: DSC1: ±5%; DSC2: 50V; DSC3: C0G; ERP Number: 1010200151; ID: 21; Manufacture: 三星|国巨|村田; Part Name: 贴片电容; Part Number: C020102120021; Price: 0.01
C114 C117 C153 C154 C179 C180 = C-0402: DSC1: ±5%; DSC2: 50V; DSC3: C0G; ERP Number: 1010200091; ID: 27; Manufacture: 三星|国巨|村田; Part Name: 贴片电容; Part Number: C020102120027; Price: 0.02
C118 C119 C190-C193 C195-C198 C208 C209 C214-C222 = C-0603: DSC1: ±20%; DSC2: 6.3V; DSC3: X5R; ERP Number: 1010200133; ID: 72; Manufacture: 三星|国巨|村田; Part Name: 贴片电容; Part Number: C020102120072; Price: 0.06
C120 C121 C124 C168 C169 C181 C206 = C-0402: DSC1: ±10%; DSC2: 10V; DSC3: X5R; ERP Number: 1010200054; ID: 64; Manufacture: 三星|国巨|村田; Part Name: 贴片电容; Part Number: C020102120064; Price: 0.02
C122 C123 C128 C161-C165 C167 C170 C173 C174 C176 C182 C187 C189 C200 C203 C212 C213 C233-C242 C259 = C-0402: DSC1: ±10%; DSC2: 10V; DSC3: X7R; ID: 60; Manufacture: 三星|国巨|村田; Part Name: 贴片电容; Part Number: C020102120060; Price: 0.01
C125 C177 C205 C243 = C-0603: DSC1: ±20%; DSC2: 10V; DSC3: X5R; ERP Number: 1010200076; ID: 71; Manufacture: 三星|国巨|村田; Part Name: 贴片电容; Part Number: C020102120071; Price: 0.05
C127 C160 C172 C175 = C-0402: DSC1: ±20%; DSC2: 10V; DSC3: X5R; ID: 67; Manufacture: 三星|国巨|村田; Part Name: 贴片电容; Part Number: C020102120067; Price: 0.04
J21 = RF-IPEX-20279: DSC1: IPEX-20279-001E-01 板端贴片天线座 U.LF接头; DSC2: 贴片; ID: 1; Part Name: IPEX座; Part Number: J110103040001
L21 = L-IND: DSC1: ±20%; DSC2: Isat=1.6A; DSC3: Irms=1.25A; DSC4: 260mΩ; DSC5: 2.5*2.0*1.2mm; DSC6: WPN252012H4R7MT(顺络); DSC7: FHD252012S-4R7MT(长江微电); DSC8: ZCRH252012-4.7uH-M(宗成); ID: 54; Manufacture: 宗成|长江微电|顺络; Part Name: 功率电感
Q10 Q12 = P-MOS: DSC1: Vds=-30V; DSC2: Id=-4.2A; DSC3: Vgs(th)=1.3V; DSC4: Vgs=±12V; DSC5: pd=350mW; ERP Number: 1010800001; ID: 1; Manufacture: 长电; Part Number: C030202190001; Price: 0.17
R180 R185 R201 R204 R207 R332 R387 R388 R392 R398-R401 = R-0402: DSC1: ±5%; DSC2: 1/16W; ERP Number: 1010200096; ID: 328; Part Name: 贴片电阻; Part Number: C011002080328; Price: 0.01
R181-R184 R186 R187 R199 R272 R275 R276 R279 R280 R282 R300-R305 R314 R328 R329 R334-R337 R344 R347-R349 R352 R382 R394 = R-0402: DSC1: ±5%; DSC2: 1/16W; ERP Number: 1010200173; ID: 262; Part Name: 贴片电阻; Part Number: C011002080262; Price: 0.01
R191 R196 R200 R205 R206 R208-R210 R296 R298 R306 R340 R341 R389 R390 R422 R423 = R-0402: DSC1: ±5%; DSC2: 1/16W; ERP Number: 1010200100; ID: 217; Part Name: 贴片电阻; Part Number: C011002080217; Price: 0.01
R202 = R-0805: DSC1: ±1%; DSC2: 1/8W; ERP Number: 1010200199; ID: 1,448; Part Name: 贴片电阻; Part Number: C011002081448; Price: 0.01
R203 R384 R385 R391 = R-0402: DSC1: ±5%; DSC2: 1/16W; ERP Number: 1010200103; ID: 353; Part Name: 贴片电阻; Part Number: C011002080353; Price: 0.01
U18 = MODULE_AP6XXX: WiFi+Bluetooth 4.0(HS)+FM Rx; Created by: JJJ; Manufacturer: Ampak（正基科技）; Manufacturer PN: AP6335; Part Type: module; Priority: A; RK PN: AP6335
XT2 = XTAL-4P: DSC1: 40Ω; DSC2: ±10ppm; DSC3: 12pF; DSC4: -40℃~+85℃; DSC5: 3.2*2.5mm 4P; ERP Number: 1010700036; ID: 7; Manufacture: 爱普生; Part Name: 贴片无源晶振; Part Number: C050102290007; Price: 0.74
C156 C157 = C-0402: DSC1: ±5%; DSC2: 50V; DSC3: C0G; ERP Number: 1010200152; ID: 40; Manufacture: 三星|国巨|村田; Part Name: 贴片电容; Part Number: C020102120040; Price: 0.01
C166 = C-0402: DSC1: ±10%; DSC2: 50V; DSC3: X7R; ERP Number: 1010200077; ID: 57; Manufacture: 三星|国巨|村田; Part Name: 贴片电容; Part Number: C020102120057; Price: 0.02
C261 = C-1206: DSC1: ±10%; DSC2: 2KV; DSC3: X7R; ERP Number: 1010200094; Manufacture: 三星|国巨|村田; Part Name: 贴片电容; Part Number: C020102120077; Price: 0.17
D58-D61 = DI-TVS-D: DSC1: 双向; DSC2: Vdc=5V; DSC4: Vc=19V; DSC5: Cj=1.2pF; ID: 10; Manufacture: 硕凯; Part Name: ESD; Part Number: C040505124709; Price: 0.06; Solder: 推荐
D81 D82 = DI-ESD-SRV05-4: DSC1: 单向; DSC2: Vrwm=5V; DSC3: VBR=6V; DSC4: Vc=13V; DSC5: Ipp=3.5A; DSC6: Ppp=45W; DSC7: Cj=0.36pF; ERP Number: 1010800050; ID: 15; Manufacture: 伯恩半导体; Part Name: TVS; Part Number: C040602260015; Price: 0.21; Solder: 量产
J23 = J-RJ45-HR911130C: DSC1: RJ45 8P插件 内置千兆变压器(商业级)  双灯 卧式 全包带弹片,16x21.3x13.5mm; DSC2: 通孔弯针; DSC4: HR911130C(汉仁); ID: 5; Part Name: RJ45; Part Number: J120103060005
L23 = L-IND: DSC1: ±20%; DSC2: Isat=2.6A; DSC3: Irms=1.9A; DSC4: 120mΩ; DSC5: 2.5*2.0*1.2mm; DSC6: WPN252012H2R2MT(顺络); DSC7: FHD252012S-2R2MT(长江微电); DSC8: ZCRH252012-2.2uH-M(宗成); ID: 53; Manufacture: 宗成|长江微电|顺络; Part Name: 功率电感
R259-R266 R307 R308 R355-R358 R360 R361 = R-0402: DSC1: ±5%; DSC2: 1/16W; ERP Number: 1010200263; ID: 238; Part Name: 贴片电阻; Part Number: C011002080238; Price: 0.01
R267 R268 = R-0402: DSC1: ±5%; DSC2: 1/16W; ERP Number: 1010200226; ID: 296; Part Name: 贴片电阻; Part Number: C011002080296; Price: 0.01
R270 R330 R412 = R-0402: DSC1: ±5%; DSC2: 1/16W; ERP Number: 1010200160; ID: 279; Part Name: 贴片电阻; Part Number: C011002080279; Price: 0.01
R271 = R-0402: DSC1: ±5%; DSC2: 1/16W; ID: 281; Part Name: 贴片电阻; Part Number: C011002080281; Price: 0.01
R273 R274 R277 R278 R281 R283-R288 R290 R291 R293 R294 = R-0402: DSC1: ±5%; DSC2: 1/16W; ERP Number: 1010200177; ID: 320; Part Name: 贴片电阻; Part Number: C011002080320; Price: 0.01
R289 = R-0402: DSC1: ±1%; DSC2: 1/16W; ERP Number: 1010200324; ID: 785; Part Name: 贴片电阻; Part Number: C011002080785; Price: 0.01
R297 = R-0402: DSC1: ±5%; DSC2: 1/16W; ID: 309; Part Name: 贴片电阻; Part Number: C011002080309; Price: 0.01
R419 = R-0805: DSC1: ±1%; DSC2: 1/8W; ERP Number: 1010200447; Part Name: 贴片电阻; Part Number: C011002081864; Price: 0.01
U20 = Ethernet_RTL8211F: Integrated 10/100/1000 Gigabit Ethernet Transceiver，Supports IEEE 802.3az-2010,; Created by: JJJ; Manufacturer: RealTek(瑞昱); Part Type: Ethernet; Priority: A
XT4 = XTAL-4P: DSC1: 40Ω; DSC2: ±10ppm; DSC3: 12pF; DSC4: -40℃~+85℃; DSC5: 3.2*2.5mm 4P; ID: 6; Manufacture: 泰晶; Part Name: 贴片无源晶振; Part Number: C050102290006; Price: 0.48
D64 D65 D79 D80 = DI-ESD: DSC1: 双向; DSC2: Vdc=12V; DSC4: Vc=40V; DSC5: Cj=0.05pF; ID: 1; Manufacture: 硕凯; Part Name: ESD; Part Number: C040504013980; Price: 0.06; Solder: 推荐
D69 D70 D90 = DI-XI-S: DSC1: VR=30V; DSC2: IF=200mA; DSC3: VF=350mV/10mA; DSC4: IR=0.5uA; ID: 2; Manufacture: 乐山无线电; Part Name: 肖特基二级管; Part Number: C040202220002; Price: 0.05; Solder: 推荐
J24 = J-HDR-D-40_0: DSC1: 双排单塑; DSC2: 2x20; DSC3: 2.54mm脚距; DSC4: 通孔直针; DSC5: 针长11.5mm 3+2.5(H塑高)+6mm; DSC6: 黑胶; DSC7: A2541WV-2x20P(CJT); ID: 64; Part Name: 双排针; Part Number: J010104013835
Q11 Q19 = N-MOS-Q: DSC1: Vds=30V; DSC2: Id=100mA; DSC3: Vgs(th)=1.5V; DSC4: Vgs=±20V; DSC5: pd=150mW; ERP Number: 1010800011; ID: 4; Manufacture: 先科; Part Name: N-MOS; Part Number: C030202190004; Price: 0.1
R309-R312 R315 R316 = RN_0402X4: DSC1: ±5%; DSC2: 1/16W; ID: 4; Part Name: 贴片排阻; Part Number: C010302090004; Price: 0.01
D71-D75 D96 = DI-ESD: DSC1: 双向; DSC2: Vdc=14V; DSC3: Vbr=300V; DSC4: Vc=30V; DSC5: Cj=0.25pF; ERP Number: 1010800023; ID: 2; Manufacture: AEM; Part Name: ESD; Part Number: C040502250002; Price: 0.06
J25 = J-A-2P: DSC1: 2p; DSC2: 1.25mm间距; DSC3: 立贴; DSC4: 米黄色胶壳 耐高温; DSC5: JLX-1.25T-2AB(九龙熹); DSC6: X9821WVS-02-9TSN(星坤); ID: 6; Part Name: MX1.25T; Part Number: J020102800058
R326 R327 = R-0402: DSC1: ±5%; DSC2: 1/16W; ERP Number: 1010200170; ID: 311; Part Name: 贴片电阻; Part Number: C011002080311; Price: 0.01
SW1 SW2 = SW-TS24CA: DSC1: 轻触开关 侧键 贴片 带定位柱; DSC2: SMD,3.5*4.5mm; DSC3: TS24CA(首韩); ID: 4; Part Name: 轻触开关; Part Number: C180102690004
U21 = U-HYM8563S: DSC1: RTC,I2C, VCC=2.0-5.5V; DSC2: TSSOP8; DSC3: -40℃~+85℃; ID: 16; Manufacture: HAOYU(昊昱); Part Name: RTC芯片; Part Number: C110204273853
XT5 = XTAL-2P: DSC1: 70kΩ; DSC2: ±20ppm; DSC3: 12.5pF; DSC4: -40℃~+85℃; DSC5: 3.2*1.5mm 2P; ID: 2; Manufacture: 泰晶; Part Name: 贴片无源晶振; Part Number: C050102290002; Price: 0.61
C183 C186 = C-0402: DSC1: ±10%; DSC2: 50V; DSC3: X7R; ERP Number: 1010200128; ID: 61; Manufacture: 三星|国巨|村田; Part Name: 贴片电容; Part Number: C020102120061; Price: 0.05
C184 C185 C188 = C-0402: DSC1: ±5%; DSC2: 50V; DSC3: C0G; ERP Number: 1010200087; Manufacture: 三星|国巨|村田; Part Name: 贴片电容; Part Number: C020102120033; Price: 0.01
C194 C199 C202 = C-0402: DSC1: ±5%; DSC2: 50V; DSC3: C0G; ERP Number: 1010200087; ID: 33; Manufacture: 三星|国巨|村田; Part Name: 贴片电容; Part Number: C020102120033; Price: 0.01
H1 = HOLE
J26 = J-MINIPCIE-52P_1: DSC1: mini pcie 52P 8.0H 镀金G/F; DSC2: 52P; DSC3: 贴片; DSC4: 91304-80-052R2(UMaxconn); ID: 3; Part Name: 金手指连接器; Part Number: J050102900003
L24 = L-IND: DSC1: ±20%; DSC2: Isat=3.6A; DSC3: Irms=3A; DSC4: 54mΩ; DSC5: 2.5*2.0*1.2mm; DSC6: WPN252012H1R0MT(顺络); DSC7: FHD252012S-1R0MT(长江微电); DSC8: ZCRH252012-1uH-M(宗成); ID: 52; Manufacture: 宗成|长江微电|顺络; Part Name: 功率电感
LED2 = D-LED0603_0: DSC1: 绿色LED，SMD,0603，VF=3V; DSC2: NCD0603G1(国星光电); DSC3: 19-217/GHC-YR1S2/3T(亿光); ERP Number: 1010800009; ID: 7; Part Name: LED; Part Number: C140202660003; Price: 0.08
R331 = R-0402: DSC1: ±5%; DSC2: 1/16W; ERP Number: 1010200258; ID: 332; Part Name: 贴片电阻; Part Number: C011002080332; Price: 0.01
R333 R359 = R-0603: DSC1: ±1%; DSC2: 1/10W; ERP Number: 1010200158; ID: 1,182; Part Name: 贴片电阻; Part Number: C011002081182; Price: 0.01
R342 R393 = R-0402: DSC1: ±5%; DSC2: 1/16W; ERP Number: 1010200104; ID: 303; Part Name: 贴片电阻; Part Number: C011002080303; Price: 0.01
R343 = R-0402: DSC1: ±1%; DSC2: 1/16W; ID: 943; Part Name: 贴片电阻; Part Number: C011002080943; Price: 0.01
R345 = R-0402: DSC1: ±1%; DSC2: 1/16W; ERP Number: 1010200140; ID: 856; Part Name: 贴片电阻; Part Number: C011002080856; Price: 0.01
SIM1 = J-SIM-021_0: DSC1: SIM卡座 91228 抽屉式 8P; DSC2: 31.0*25.1*26mm; DSC3: 贴片; DSC4: SIM-021(硕方); ERP Number: 1040100109; ID: 5; Part Name: SIM卡座; Part Number: J080202990002
U22 = U-ETA3417_1: DSC1: Vi=2.6-7.0V; DSC2: Vo=0.6-7.0V; DSC3: Io=2.5A; DSC4: Vfb=0.6V; DSC6: 3MHz; DSC7: 同步降压; DSC8: 替代料：TI的TLV62569DBVR/矽力杰SY8089AAAC; ID: 43; Manufacture: 钰泰; Part Name: DCDC; Part Number: C070205183984; Solder: 量产
J27 = J-M2_NGFF-M-KEY_1: DSC1: M2_NGFF-M座子,0.5mm Pitch,H=8.5mm; DSC2: 67P; DSC3: 贴片; DSC4: 91302-85-067RDM(Umaxconn); DSC5: APCI0164-P001A(LOTES); ID: 31; Part Name: 金手指连接器; Part Number: J050111093948
C244 C246 = C-0603: DSC1: ±10%; DSC2: 50V; DSC3: X5R; ERP Number: 1010200142; ID: 69; Manufacture: 三星|国巨|村田; Part Name: 贴片电容; Part Number: C020102120069; Price: 0.04
C245 C247 C257 = C-0805: DSC1: ±10%; DSC2: 25V; DSC3: X5R; ERP Number: 1010200144; ID: 74; Manufacture: 三星|国巨|村田; Part Name: 贴片电容; Part Number: C020102120074; Price: 0.09
D76 D77 = DI-ESD-SE05NRC14GA: DSC1: 双向; DSC2: Vdc=5V; DSC3: Vbr=8V; DSC4: Vc=20V; DSC5: Cj=0.4pF; ID: 8; Manufacture: 硕凯; Part Name: ESD; Part Number: C040504013981; Price: 0.15; Solder: 推荐
J28 = J-HDR-D-20: DSC1: 双排单塑; DSC2: 2x10; DSC3: 2mm脚距; DSC4: 通孔弯针; DSC5: 2.8+2(H塑高)+4 mm; DSC6: 黑胶; DSC7: X4621WR-2x10I-C28D40（星坤）; ID: 29; Part Name: 双排针; Part Number: J010102760085
J29 = J-HDR-6: DSC1: 单排单塑; DSC2: 1x6; DSC3: 2mm脚距; DSC4: 通孔直针; DSC5: 针长8.8mm  2.8+2(H塑高)+4 mm; DSC6: 黑胶; DSC7: X4611WV-06I-C28D40（星坤）; ID: 66; Part Name: 单排针; Part Number: J010206123880
J30 = J-H-6P: DSC1: 6p; DSC2: 2.0mm间距; DSC3: 通孔90度弯针; DSC4: 米黄色胶壳 耐高温; DSC5: JLX-PH20-6B（九龙熹）; DSC6: X2016WR-06-46SN(星坤); ID: 20; Part Name: PH; Part Number: J020302820024
Q13 = N-MOS-Q: DSC1: Vds=30V; DSC2: Id=100mA; DSC3: Vgs(th)=1.5V; DSC4: Vgs=±20V; DSC5: pd=150mW; ERP Number: 1010800011; Manufacture: 先科; Part Name: N-MOS; Part Number: C030202190004; Price: 0.1
U25 = U-74LVC1G125GW-125: DSC1: 1位 高速缓冲 三态输出 VCC=1.65V-5.5V; DSC2: SOT-353; DSC3: -55℃~+125℃; ERP Number: 1010100128; ID: 5; Manufacture: Nexperia(安世); Part Name: 逻辑缓冲器; Part Number: C080302460001; Price: 0.13

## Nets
GND: C112.1 C114.2 C115.1 C116.1 C117.1 C118.1 C119.1 C120.1 C121.1 C122.1 C123.1 C125.1 C126.1 C127.1 C128.1 C153.1 C154.1 C155.1 C156.1 C157.1 C158.1 C159.1 C160.1 C161.1 C162.1 C163.1 C164.2 C165.1 C166.1 C167.1 C168.2 C169.1 C170.1 C171.1 C172.1 C173.1 C174.1 C175.1 C176.2 C177.2 C179.1 C180.1 C181.1 C182.1 C183.2 C184.2 C185.2 C186.2 C188.2 C190.1 C191.1 C192.1 C193.1 C194.1 C195.1 C196.1 C197.1 C198.1 C199.1 C200.1 C201.1 C202.1 C203.1 C204.1 C205.1 C206.1 C208.1 C209.1 C214.1 C215.1 C216.1 C217.1 C218.1 C219.1 C220.1 C221.1 C222.1 C243.1 C244.1 C245.1 C247.1 C259.1 C261.1 D64.2(I/O1) D65.2(I/O1) D71.2(I/O1) D72.2(I/O1) D73.2(I/O1) D74.2(I/O1) D75.2(I/O1) D76.3 D76.8 D77.3 D77.8 D79.2(I/O1) D80.2(I/O1) D81.2 D82.2 D96.2(I/O1) H1.1 J21.1(GND1) J21.3(GND2) J21.4(GND3) J23.10(GND) J24.5 J24.6 J24.24 J24.33 J24.34 J25.2 J25.3 J25.4 J26.4(GND) J26.9(GND) J26.15(GND) J26.18(GND) J26.21(GND) J26.26(GND) J26.27(GND) J26.29(GND) J26.34(GND) J26.35(GND) J26.37(GND) J26.40(GND) J26.43(GND) J26.50(GND) J26.55(GND) J26.56(GND) J27.1(GND) J27.3(GND) J27.9(GND) J27.15(GND) J27.21(GND) J27.27(GND) J27.33(GND) J27.39(GND) J27.45(GND) J27.51(GND) J27.57(GND) J27.71(GND) J27.73(GND) J27.75(GND) J27.G1(EHT1) J27.G2(EHT2) J27.G3(G4) J27.G4(G3) J28.4 J28.13 J28.14 Q13.2(SOURCE) R201.2 R208.1 R268.2 R271.1 R273.1 R277.1 R281.1 R284.1 R286.1 R287.1 R289.1 R290.1 R293.1 R345.1 R385.2 R419.1 SIM1.C5(GND) SW1.1 SW1.2 SW1.4 SW2.1 SW2.2 SW2.4 U18.1(GND1) U18.3(GND2) U18.20(GND3) U18.31(GND4) U18.33(GND5) U18.36(GND6) U20.41(E_Pad) U21.4(VSS) U22.2(GND) U25.1(~{OE}) U25.3(GND) XT2.2 XT2.4 XT4.2 XT4.4 ; also on sheet 4 5 6 7 8 9 10 11 12 13
GND_EARTH: C261.2 J23.SH1 J23.SH2 R419.2 ; also on sheet 4 13
GND_IN: C257.1 J30.1 J30.2 ; also on sheet 4 11
VBAT_RTC: D70.A J25.1
VBAT_WL_1T1R: C118.2 C119.2 C125.2 Q10.3(DRAIN) R202.2 U18.9(VBAT)
VCC3V3_PHY1: C172.2 C173.2 C174.2 C175.2 C176.1 R274.2 R278.2 R306.2 U20.11(AVDD33) U20.29(DVDD33) U20.40(AVDD33)
VCC12V_DCIN: C257.2 J29.1 J30.5 J30.6 ; also on sheet 4 11
VCC_1V8: Q19.1(GATE) R200.1 R298.1 R398.1 R399.1 ; also on sheet 5 7 9 11 12 13
VCC_3V8: C190.2 C191.2 C192.2 C193.2 C194.2 C195.2 C196.2 C197.2 C198.2 C199.2 C200.2 C201.2 C202.2 C203.2 C204.2 C207.2 C208.2 C209.2 J26.2(VCC3V3) J26.24(NC3) J26.39(VCC3V3) J26.41(VCC3V3) J26.52(VCC3V3) L24.2 R342.2 R343.2
VCC_5V: C177.1 C205.2 C206.2 C244.2 J24.35 J24.36 J29.3 Q11.1(GATE) R388.1 U22.4(VIN) U25.5(Vcc) ; also on sheet 4 7 8 9 11
VCC_EDP_OUT: C245.2 C246.2 J29.2 J29.4 J29.6 Q12.2(SOURCE) R391.2
VCC_EDP_OUT_: C247.2 J28.1 J28.2 Q12.3(DRAIN)
VCCIO_PHY1: C168.1 C169.2 C170.2 R283.2 R285.2 R288.2 R291.2 R294.2 R297.2 R298.2 U20.28(DVDD_RG)
VCCIO_WL: C120.2 C121.2 C122.2 R180.1 R185.1 R200.2 R204.1 U18.22(VDDIO)
VDD3V3_PCIE30: C214.2 C215.2 C216.2 C217.2 C218.2 C219.2 C220.2 C221.2 C222.2 J27.2(3.3V) J27.4(3.3V) J27.12(3.3V) J27.14(3.3V) J27.16(3.3V) J27.18(3.3V) J27.70(3.3V) J27.72(3.3V) J27.74(3.3V) R359.2
VDD10_PHY1: C160.2 C161.2 C162.2 C163.2 C164.1 C165.2 L23.2 U20.3(AVDD10) U20.8(AVDD10) U20.21(DVDD10) U20.38(AVDD10)
VDD_3V3: C123.2 C124.2 C243.2 D69.A J28.19 J29.5 Q10.2(SOURCE) R202.1 R203.2 R267.2 R306.1 R326.2 R327.2 R359.1 R384.1 R387.1 R400.1 R401.1 ; also on sheet 4 7 8 9 10 11 12 13
VDD_RTC: C181.2 D69.C D70.C U21.8(VDD)
4G_PWREN_H_GPIO0_D5: R344.1 ; also on sheet 5
4G_RESET_L_GPIO0_D4: R337.2 ; also on sheet 5
5G_SSRXN: J26.23(UART1_CTS) R423.2
5G_SSRXP: J26.25(UART1_RFR) R422.2
5G_SSTXN: C187.2 J26.31(UART1_DTR)
5G_SSTXP: C189.2 J26.33(UART1_DCD)
BT_REG_ON_H_GPIO1_D4: R209.1 ; also on sheet 5
BT_WAKE_HOST: R199.2 U18.7(BT_HOST_WAKE)
BT_WAKE_HOST_H_GPIO2_C1: R199.1 ; also on sheet 5
CAN1_RX: J24.18 R310.5
CAN1_RX_M0: R310.4 ; also on sheet 5
CAN1_TX: J24.17 R310.6
CAN1_TX_M0: R310.3 ; also on sheet 5
CAN2_RX: D90.C J24.20 R401.2
CAN2_RX_M0: D90.A R398.2 ; also on sheet 5
CAN2_TX: J24.19 Q19.3(DRAIN) R400.2
CAN2_TX_M0: Q19.2(SOURCE) R399.2 ; also on sheet 5
CLK_32K_OUT: J27.68(SUSCLK(32kHz)(I)(3.3V)) R352.2
CLK_32K_OUT_GPIO0_B0: R352.1 ; also on sheet 5
DM4: J26.36(USB_D-) R340.1
DM_1: D65.1(I/O2) J24.31 R307.2
DP4: J26.38(USB_D+) R341.1
DP_1: D64.1(I/O2) J24.32 R308.2
EDP_EN_H_GPIO0_C5: R393.2 ; also on sheet 5
EDP_ON_: J30.4 Q11.2(SOURCE) R388.2 R389.2
EDP_ON_GPIO0_C3: Q11.3(DRAIN) R387.2 R389.1 ; also on sheet 5
EDP_PWM7: R390.1 U25.2(A) ; also on sheet 5
EDP_PWM7_: J30.3 R390.2 U25.4(Y)
EDP_TX_AUXN: C235.2 ; also on sheet 5
EDP_TX_AUXN_: C235.1 D77.4 D77.7 J28.15 R384.2
EDP_TX_AUXP: C236.2 ; also on sheet 5
EDP_TX_AUXP_: C236.1 D77.5 D77.6 J28.16 R385.1
EDP_TX_D0N: C241.2 ; also on sheet 5
EDP_TX_D0N_: C241.1 D76.1 D76.10 J28.7
EDP_TX_D0P: C242.2 ; also on sheet 5
EDP_TX_D0P_: C242.1 D76.2 D76.9 J28.8
EDP_TX_D1N: C239.2 ; also on sheet 5
EDP_TX_D1N_: C239.1 D76.4 D76.7 J28.9
EDP_TX_D1P: C240.2 ; also on sheet 5
EDP_TX_D1P_: C240.1 D76.5 D76.6 J28.10
EDP_TX_D2N: C237.2 ; also on sheet 5
EDP_TX_D2N_: C237.1 D77.1 D77.10 J28.11
EDP_TX_D2P: C238.2 ; also on sheet 5
EDP_TX_D2P_: C238.1 D77.2 D77.9 J28.12
EDP_TX_D3N: C233.2 ; also on sheet 5
EDP_TX_D3N_: C233.1 D80.1(I/O2) J28.17
EDP_TX_D3P: C234.2 ; also on sheet 5
EDP_TX_D3P_: C234.1 D79.1(I/O2) J28.18
FE1_1_DM1: R307.1 ; also on sheet 7
FE1_1_DM4: R340.2 ; also on sheet 7
FE1_1_DP1: R308.1 ; also on sheet 7
FE1_1_DP4: R341.2 ; also on sheet 7
GMAC1_MCLKINOUT_M1: C155.2 R270.1 R271.2 ; also on sheet 5
GMAC1_MDC_M1: U20.13(MDC) ; also on sheet 5
GMAC1_MDIO_M1: R297.1 U20.14(MDIO) ; also on sheet 5
GMAC1_RSTn_GPIO2_D7: R296.1 ; also on sheet 5
GMAC1_RXCLK_M1: C171.2 R304.2 ; also on sheet 5
GMAC1_RXD0_M1: R300.2 ; also on sheet 5
GMAC1_RXD1_M1: R301.2 ; also on sheet 5
GMAC1_RXD2_M1: R302.2 ; also on sheet 5
GMAC1_RXD3_M1: R303.2 ; also on sheet 5
GMAC1_RXDV_CRS_M1: R305.2 ; also on sheet 5
GMAC1_TXCLK_M1: C158.2 R282.1 ; also on sheet 5
GMAC1_TXCLK_M1_: C159.2 R282.2 U20.20(TXC)
GMAC1_TXD0_M1: R272.1 ; also on sheet 5
GMAC1_TXD0_M1_: R272.2 U20.18(TXD0)
GMAC1_TXD1_M1: R275.1 ; also on sheet 5
GMAC1_TXD1_M1_: R275.2 U20.17(TXD1)
GMAC1_TXD2_M1: R276.1 ; also on sheet 5
GMAC1_TXD2_M1_: R276.2 U20.16(TXD2)
GMAC1_TXD3_M1: R279.1 ; also on sheet 5
GMAC1_TXD3_M1_: R279.2 U20.15(TXD3)
GMAC1_TXEN_M1: R280.1 ; also on sheet 5
GMAC1_TXEN_M1_: R280.2 U20.19(TXCTL)
HOLE1: J27.76(HOLE1)
HOLE2: J27.77(HOLE2)
HOST_WAKE_BT: R394.2 U18.6(BT_WAKE)
HOST_WAKE_BT_H_GPIO1_D3: R394.1 ; also on sheet 5
I2C1_SCL: R311.2 ; also on sheet 5
I2C1_SCL_: J24.22 R311.7
I2C1_SDA: R311.1 ; also on sheet 5
I2C1_SDA_: J24.21 R311.8
I2C5_SCL_M0: R327.1 R328.2 ; also on sheet 5 12
I2C5_SDA_M0: R326.1 R329.2 ; also on sheet 5 12
I2C_SCL_RTC: R328.1 U21.6(SCL)
I2C_SDA_RTC: R329.1 U21.5(SDA)
LAN1_A+: D61.A(I/O2) D82.4 J23.2(MDI_0+) R266.2
LAN1_A-: D61.C(I/O1) D82.3 J23.3(MDI_0-) R265.2
LAN1_B+: D60.A(I/O2) D82.6 J23.4(MDI_1+) R264.2
LAN1_B-: D60.C(I/O1) D82.1 J23.7(MDI_1-) R263.2
LAN1_C+: D59.A(I/O2) D81.4 J23.5(MDI_2+) R262.2
LAN1_C-: D59.C(I/O1) D81.3 J23.6(MDI_2-) R261.2
LAN1_D+: D58.A(I/O2) D81.6 J23.8(MDI_3+) R260.2
LAN1_D-: D58.C(I/O1) D81.1 J23.9(MDI_3-) R259.2
NTC_SARADC_VIN3: R312.2 ; also on sheet 5
PCIE20_CLKREQn_3V3_L: J27.52(PCIE_CLKREQ#(IO)(3.3V)) R348.2
PCIE20_CLKREQn_M2_3V3_L: R348.1 ; also on sheet 5
PCIE20_PERSTn_3V3_L: J27.50(PCIE_PERST#(I)(3.3V)) R347.2
PCIE20_PERSTn_M2_3V3_L: R347.1 ; also on sheet 5
PCIE20_PRSNT_3V3_L: J27.69(PEDET(NC-PCIe)(GND-SATA)) R382.1
PCIE20_PRSNT_3V3_L_GPIO3_A6: R382.2 ; also on sheet 5
PCIE20_REFCLKN: R360.1 ; also on sheet 5
PCIE20_REFCLKN_: J27.53(REFCLKN) R360.2
PCIE20_REFCLKP: R361.1 ; also on sheet 5
PCIE20_REFCLKP_: J27.55(REFCLKP) R361.2
PCIE20_RXN: R355.1 ; also on sheet 5
PCIE20_RXN_: J27.41(PETn0/SATA-B+) R355.2
PCIE20_RXP: R356.1 ; also on sheet 5
PCIE20_RXP_: J27.43(PETp0/SATA-B-) R356.2
PCIE20_TX_N: C212.2 R357.1
PCIE20_TX_P: C213.2 R358.1
PCIE20_TXN: C212.1 ; also on sheet 5
PCIE20_TXN_: J27.47(PERn0/SATA-A-) R357.2
PCIE20_TXP: C213.1 ; also on sheet 5
PCIE20_TXP_: J27.49(PERp0/SATA-A+) R358.2
PCIE20_WAKEn_3V3_L: J27.54(PCIE_PEWake#(IO)(3.3V)) R349.2
PCIE20_WAKEn_M2_3V3_L: R349.1 ; also on sheet 5
PHY1_CLKOUT125: R270.2 U20.35(CLKOUT)
PHY1_G_LED-: J23.12(G_LED-) R268.1
PHY1_LED0/CFG_EXT: R273.2 R274.1 U20.32(LED0/CFG_EXT)
PHY1_LED1/CFG_LDO0: C157.2 J23.11(G_LED+) R281.2 U20.33(LED1/CFG_LDO0)
PHY1_LED2/CFG_LDO1: C156.2 J23.13(Y_LED-) R277.2 R278.1 U20.34(LED2/CFG_LDO1)
PHY1_MDI0+: R266.1 U20.1(MDI[0]+)
PHY1_MDI0-: R265.1 U20.2(MDI[0]-)
PHY1_MDI1+: R264.1 U20.4(MDI[1]+)
PHY1_MDI1-: R263.1 U20.5(MDI[1]-)
PHY1_MDI2+: R262.1 U20.6(MDI[2]+)
PHY1_MDI2-: R261.1 U20.7(MDI[2]-)
PHY1_MDI3+: R260.1 U20.9(MDI[3]+)
PHY1_MDI3-: R259.1 U20.10(MDI[3]-)
PHY1_REG_OUT: L23.1 U20.30(REG_OUT)
PHY1_RSTn: C167.2 R296.2 U20.12(PHYRSTB)
PHY1_RXCLK/PHYAD1: R284.2 R285.1 R304.1 U20.27(RXC/PHYAD1)
PHY1_RXD0/RXDLY: R287.2 R288.1 R300.1 U20.25(RXD0/RXDLY)
PHY1_RXD1/TXDLY: R290.2 R291.1 R301.1 U20.24(RXD1/TXDLY)
PHY1_RXD2/PLLOFF: R293.2 R294.1 R302.1 U20.23(RXD2/PLLOFF)
PHY1_RXD3/PHYAD0: R283.1 R303.1 U20.22(RXD3/PHYAD0)
PHY1_RXDV/PHYAD2: R286.2 R305.1 U20.26(RXCTL/PHYAD2)
PHY1_XTALIN: C153.2 U20.36(XTAL_IN) XT4.3
PHY1_XTALOUT: C154.2 U20.37(XTAL_OUT/EXT_CLK) XT4.1
PHY1_Y_LED+: J23.14(Y_LED+) R267.1
PWM3_IR: R311.3 ; also on sheet 5
PWM3_IR_: J24.23 R311.6
PWRON: J24.25 R314.2
RESET: J24.26 R311.5
RK809-CLK32K: R205.1 ; also on sheet 5
RK809_PWRON: C259.2 R314.1 R412.1 ; also on sheet 5
RSET1: R289.2 U20.39(RSET)
RTCIC_32KOUT: R206.1 U21.7(CLKOUT)
SARADC_VIN0_: J24.27 R312.8
SARADC_VIN0_KEY/RECOVERY: C182.2 R312.1 R330.1 ; also on sheet 5
SARADC_VIN2_: J24.29 R312.6
SARADC_VIN2_HP_HOOK: R312.3 ; also on sheet 5
SARADC_VIN3_: J24.28 R312.7
SARADC_VIN4: R312.4 ; also on sheet 5
SARADC_VIN4_: J24.30 R312.5
SDMMC2_CLK_M0: R187.1 ; also on sheet 5
SDMMC2_CMD_M0: R185.2 R186.1 ; also on sheet 5
SDMMC2_D0_M0: R180.2 R181.1 ; also on sheet 5
SDMMC2_D1_M0: R182.1 ; also on sheet 5
SDMMC2_D2_M0: R183.1 ; also on sheet 5
SDMMC2_D3_M0: R184.1 ; also on sheet 5
SPI0_CLK: J24.3 R315.6
SPI0_CLK_M1: R315.3 ; also on sheet 5
SPI0_CS0: J24.4 R315.5
SPI0_CS0_M1: R315.4 ; also on sheet 5
SPI0_MISO: J24.2 R315.7
SPI0_MISO_M1: R315.2 ; also on sheet 5
SPI0_MOSI: J24.1 R315.8
SPI0_MOSI_M1: R315.1 ; also on sheet 5
SYS_RESETn: R311.4 ; also on sheet 5
UART0_CTSn: R310.2 ; also on sheet 5
UART0_CTSn_: J24.16 R310.7
UART0_RTSn: R310.1 ; also on sheet 5
UART0_RTSn_: J24.15 R310.8
UART0_RX: R309.3 ; also on sheet 5
UART0_RX_: J24.14 R309.6
UART0_TX: R309.4 ; also on sheet 5
UART0_TX_: J24.13 R309.5
UART4_RX: J24.12 R309.7
UART4_RX_M1: R309.2 ; also on sheet 5
UART4_TX: J24.11 R309.8
UART4_TX_M1: R309.1 ; also on sheet 5
UART5_RX: J24.10 R316.6
UART5_RX_M1: R316.3 ; also on sheet 5
UART5_TX: J24.9 R316.5
UART5_TX_M1: R316.4 ; also on sheet 5
UART7_RX: J24.7 R316.8
UART7_RX_M1: R316.1 ; also on sheet 5
UART7_TX: J24.8 R316.7
UART7_TX_M1: R316.2 ; also on sheet 5
UART8_CTSn_M0: R201.1 U18.41(UART_RTS_N) ; also on sheet 5
UART8_RTSn_M0: U18.44(UART_CTS_N) ; also on sheet 5
UART8_RX_M0: U18.42(UART_TXD) ; also on sheet 5
UART8_TX_M0: U18.43(UART_RXD) ; also on sheet 5
USB3_HOST1_SSRXN: R423.1 ; also on sheet 5 7
USB3_HOST1_SSRXP: R422.1 ; also on sheet 5 7
USB3_HOST1_SSTXN: C187.1 ; also on sheet 5 7
USB3_HOST1_SSTXP: C189.1 ; also on sheet 5 7
USIM_CLK: C185.1 D75.1(I/O2) R335.2 SIM1.C3(CLK)
USIM_CLK_: J26.12(USIM_CLK) R335.1
USIM_DATA: C188.1 D73.1(I/O2) R331.1 R334.2 SIM1.C7(DATA)
USIM_DATA_: J26.10(USIM_IO) R334.1
USIM_RST: C184.1 D72.1(I/O2) R332.2 R336.2 SIM1.C2(RESET)
USIM_RST_: J26.14(USIM_RESET) R336.1
USIM_VDD: C183.1 C186.1 D74.1(I/O2) R331.2 R332.1 R333.2 SIM1.C1(VDD)
WIFI1T1R_CLK: C112.2 R187.2 U18.17(SDIO_DATA_CLK)
WIFI1T1R_CMD: R186.2 U18.16(SDIO_DATA_CMD)
WIFI1T1R_D0: R181.2 U18.18(SDIO_DATA_0)
WIFI1T1R_D1: R182.2 U18.19(SDIO_DATA_1)
WIFI1T1R_D2: R183.2 U18.14(SDIO_DATA_2)
WIFI1T1R_D3: R184.2 U18.15(SDIO_DATA_3)
WIFI1T1R_XTAL_IN: C114.1 U18.10(XTAL_IN) XT2.3
WIFI1T1R_XTAL_OUT: R191.2 U18.11(XTAL_OUT)
WIFI_PWREN_L_GPIO0_B7: R207.2 ; also on sheet 5
WIFI_REG_ON_H_GPIO3_D5: R196.1 R210.1 ; also on sheet 5
WIFI_WAKE_HOST_H_GPIO3_D4: U18.13(WL_HOST_WAKE) ; also on sheet 5
WIFIBT_32KIN_1T1R: C126.2 R204.2 R205.2 R206.2 U18.24(LPO)
N17053074: C113.2 C115.2 U18.2(WL_BT_ANT)
N17053234: C113.1 C116.2 J21.2(SIG)
N68563646: C179.2 U21.1(OSCI) XT5.2
N68563661: C180.2 U21.2(OSCO) XT5.1
N69853313: C246.1 Q12.1(GATE) R391.1 R392.1
N69853352: Q13.3(DRAIN) R392.2
N69854514: Q13.1(GATE) R393.1
N69863572: C117.2 R191.1 XT2.1
N69863896: R209.2 R210.2 U18.34(BT_RST_N)
N69864199: R208.2 U18.29(VDD_TCXO)
N69864441: R196.2 U18.12(WL_REG_ON)
N69864462: C127.2 C128.2 L21.2 U18.23(VIN_LDO)
N69864477: L21.1 U18.21(VIN_LDO_OUT)
N69866041: C124.1 Q10.1(GATE) R203.1 R207.1
N69883193: C166.2 J23.1(CT1/2/3/4)
N69887528: L24.1 U22.3(SW)
N69887530: C207.1 R343.1 R345.2 U22.5(FB)
N69887600: R344.2 U22.1(EN)
N69896427: J26.8(VREG_USIM) R333.1
N69897118: J26.22(PERST_N) R337.1
N69899428: J26.42(LED_WWAN) LED2.2(CATHODE)
N69899460: LED2.1(ANODE) R342.1
N69910248: D71.1(I/O2) R330.2 SW1.3
N70064377: D96.1(I/O2) R412.2 SW2.3

Not connected (* = marked no-connect by the designer): D81 5*; D82 5*; J26 1(MICP)* 3(MICN)* 5(EARP)* 6(NC1)* 7(EARN)* 11(UART1_RX)* 13(UART1_TX)* 16(NC2)* 17(UART1_R1)* 19(WAKEUP_N)* 20(W_DISABLE_N)* 28(NC4)* 30(UART2_RFR)* 32(UART2_CTS)* 44(UART2_RX)* 45(AUX_PCM_CLK)* 46(UART2_TX)* 47(AUX_PCM_DOUT)* 48(NC5)* 49(AUX_PCM_DIN)* 51(AUX_PCM_SYNC)* 53(MT1)* 54(MT2)*; J27 5(PETn3)* 6(N/C_06)* 7(PETp3)* 8(N/C_08)* 10(DAS/DSS#(O)(OD))* 11(PERn3)* 13(PERp3)* 17(PETn2)* 19(PETp2)* 20(N/C)* 22(N/C)* 23(PERn2)* 24(N/C)* 25(PERp2)* 26(N/C)* 28(N/C)* 29(PETn1) 30(N/C)* 31(PETp1) 32(N/C)* 34(N/C)* 35(PERn1) 36(N/C)* 37(PERp1) 38(DEVSLP(I)(3.3V)) 40(N/C)* 42(N/C)* 44(N/C)* 46(N/C)* 48(N/C)* 56(Reserved/MFG_Data)* 58(Reserved/MFG_Clock)* 67(N/C)*; J28 3 5 6 20; SIM1 C6(VPP)* CD1 CD2; U18 4(FM_RX)* 5(N_WAKE)* 8(BT_VIO/N_HOST_WAKE)* 25(PCM_OUT) 26(PCM_CLK) 27(PCM_IN) 28(PCM_SYNC) 30(TCXO_IN)* 32(GPS_RF)* 35(N_I2C_SDA)* 37(N_I2C_SCL)* 38(N_REG_PU)* 39(TX2)* 40(TX1)* 45(N_VDDSWPIO)* 46(N_VDDSWP_OUT)* 47(N_VDDSWP_IN)*; U20 31(INTB/PMEB); U21 3(\~{IN}T)

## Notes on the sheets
sheet 14
- Giga PHY1
- RGMII Power Source
- CFG_EXT
- CFG_LDO[1:0]
- External 3.3V
- 1'b1
- 2'b00
- External 1.8V
- 1'b1
- 2'b10
- Internal 1.8V (default)
- 1'b0
- 2'b10
- 3.3Vpp
- Reserve for EMI.
- Reserve for EMI.
- MAC <----- PHY
- VCC_PHY0_IO Voltage Config
- Close to SOC
- PHY Address Config
- PHY Address
- PHYAD[2:0]
- 1 (default)
- 3'b001
- Pull-up for additional 2ns delay to RXC for data latching
- Pull-up for additional 2ns delay to TXC for data latching
- Pull-up to disable PLL @ ALDPS mode(Low power mode)
- Close to PIN21
- Close to PIN30
- RTL8211F-CG(SW Mode)
- RTL8211FI-CG(SW Mode)Industrial
- Close to PIN3,8,38
- RTL8211F-CG(SW Mode)
- RTL8211FI-CG(SW Mode)Industrial
- Note:
- According to the actual
  choice of mounted
  Cannot be mounted
  at the same time
- PHYRSTB is 3.3V IO
- Close to PIN28
- Close to PIN11,40
- Close to PHY
- Close to PIN29
sheet 15
- Extension ports
- 3.3V
- 3.3V
- 3.3V
- 3.3V
sheet 16
- PCIE2.0 module
- Place close to power pin of Mini PCIE Card
sheet 17
- EDP_TX
- Backlight Power
sheet 18
- SIM CARD
- 4G module PCIe
- 4G/5G_POWER
- Vout=（1+R1/R2）× 0.6V
sheet 19
- RTC IC
- RECOVERY
- POWER ON
- ADC=9
sheet 20
- SDIO WIFI/BT MODULE
- 50 Ohm RF trace
- Note:
  Adjusted the load capacitance
  according to the crystal specification.
- Option1
- Using RTL8189ETV/FTV modules，
  please notice
  WIFI REG ON is on pin12 or pin34,
  choose
  according to the actual condition.
- Note:
- According to the actual
  choice of mounted
  Cannot be mounted at the same time
- Please choose IO voltage values
  according to the real mounted module
  and modify the corresponding
  software configuration.
- For RTL8723DS
- The maximum peak current is 600mA
  Close to WIFI module
- Option4
- Option2
- 1A_DCR<=80mohm
- For RTL8821CS
- WIFI
- OPTION
- a
- b/g/n
- ac
- 5GHz
- BT
- Crystals
- VDDIO
- Option1
- Option2
- Option3
- Option4
- Option3
- Yes@SDIO2.0
  No@SDIO3.0
- AW-CM256SM
- Yes
- Yes
- Yes
- Yes
- 4.2
- 37.4MHz
- 1.71-3.6V
- Yes
- Yes
- Yes
- AP6236/AP6212
- No
- Yes
- No
- No
- 4.2/4.0
- 26MHz
- 1.71-3.6V
- Yes
- Yes
- No
- Yes
- Using RTL8189ETV/FTV modules，please notice
  WIFI REG ON is on pin12 or pin34, choose
  according to the actual condition.
- Yes@SDIO2.0
  No@SDIO3.0
- AP6256/AP6255
- Yes
- Yes
- Yes
- Yes
- 5.0/4.2
- 37.4MHz
- 1.71-3.6V
- Yes
- Yes
- Yes
- RTL8189ETV
  Module F89FTSM12-W3
- No
- Yes
- No
- No
- No
- Module
  Integrated
- 1.8-3.3V
- No
- No
- No
- No
- RTL8723BS
  Module F23BDSM23-W2
- No
- Yes
- No
- No
- 4.0
- Module
  Integrated
- 1.62-3.6V
- No
- No
- No
- No
- Note:
  Yes: option circuit be mounted
  No:  option circuit not be mounted
- RTL8723DS
  Module 6223A-SRD
- No
- Yes
- No
- No
- 4.2
- Module
  Integrated
- 1.62-3.6V
- No
- No
- No
- No
- QCA9377
  Module 8223A-SR
- Yes
- Yes
- Yes
- Yes
- 4.2
- Module
  Integrated
- 1.7-3.45V
- No
- No
- No
- Yes
- RTL8821CS
  Module 6221A-SRC
- Yes
- Yes
- Yes
- Yes
- 4.2
- Module
  Integrated
- 1.7-3.45V
- No
- No
- No
- No
